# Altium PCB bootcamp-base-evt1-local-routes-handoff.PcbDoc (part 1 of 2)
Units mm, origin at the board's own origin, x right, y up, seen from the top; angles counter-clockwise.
Board outline 49.31 x 77.41 mm, 4 copper layers (Top Layer, Internal Plane 1, Internal Plane 2, Bottom Layer), stack 1.597 mm thick; 167 components, 119 nets, 1376 pads, 238 vias.
Unrouted connection lines stored in the file: 50.
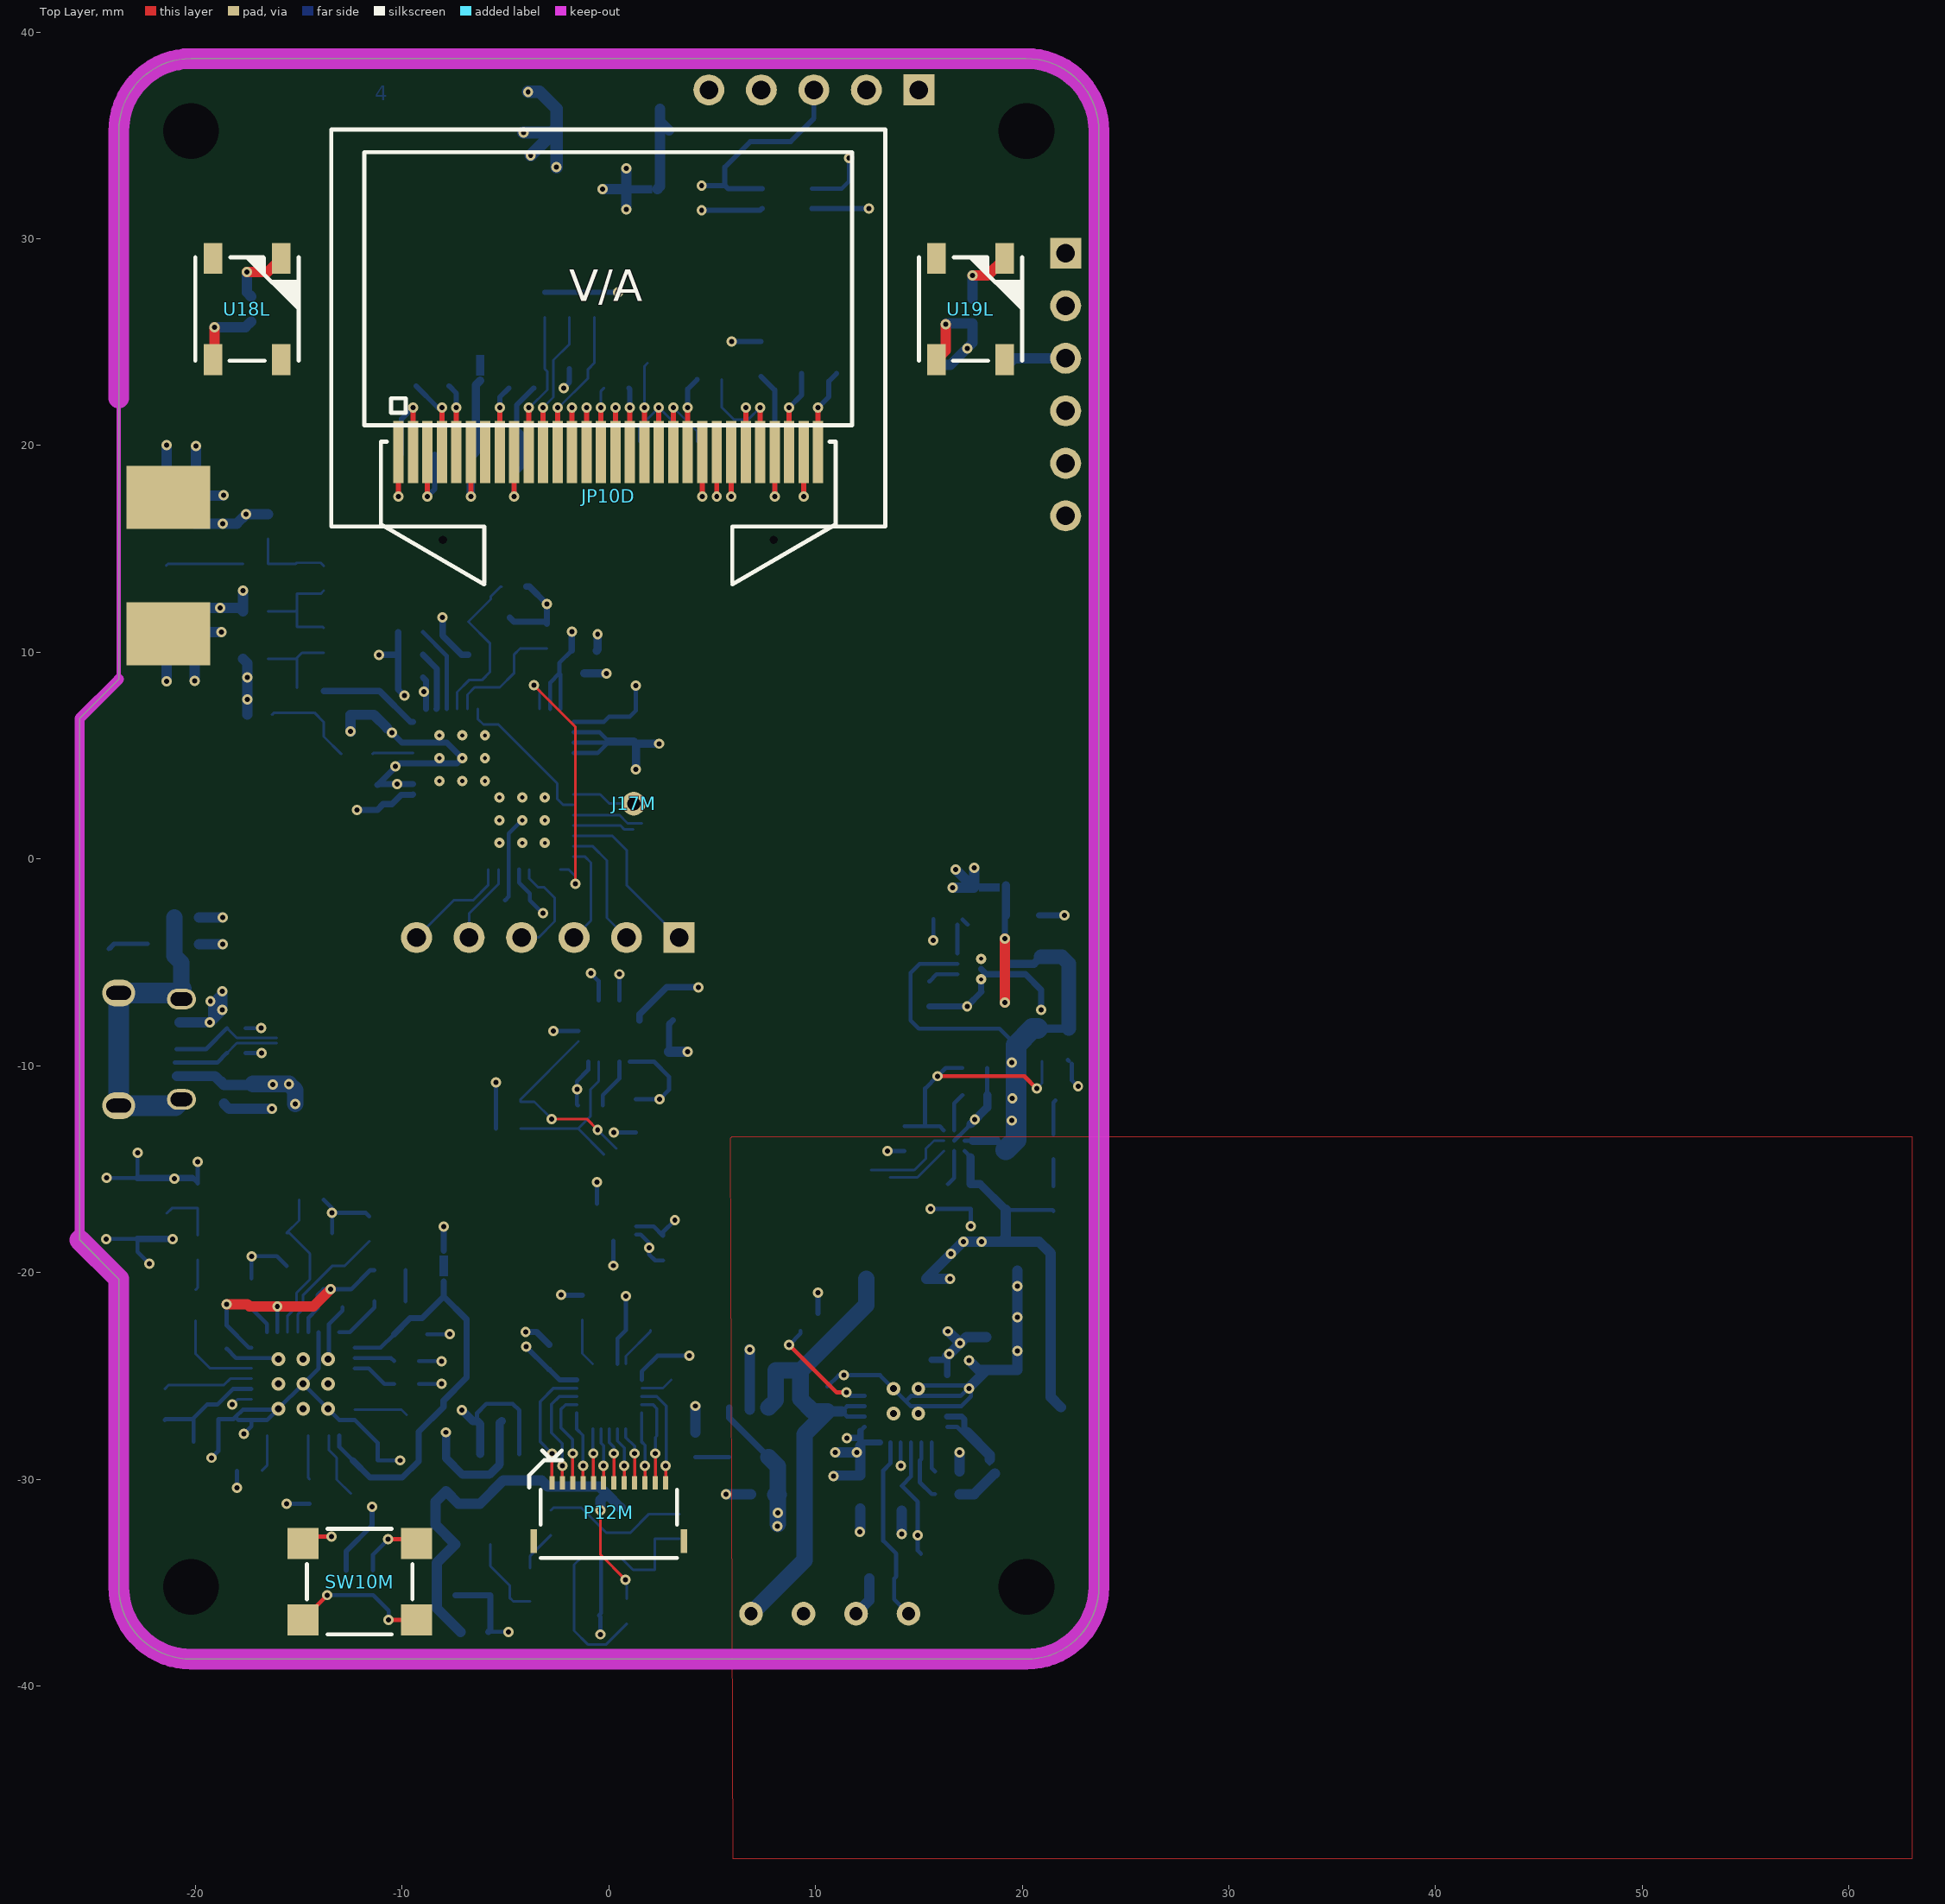
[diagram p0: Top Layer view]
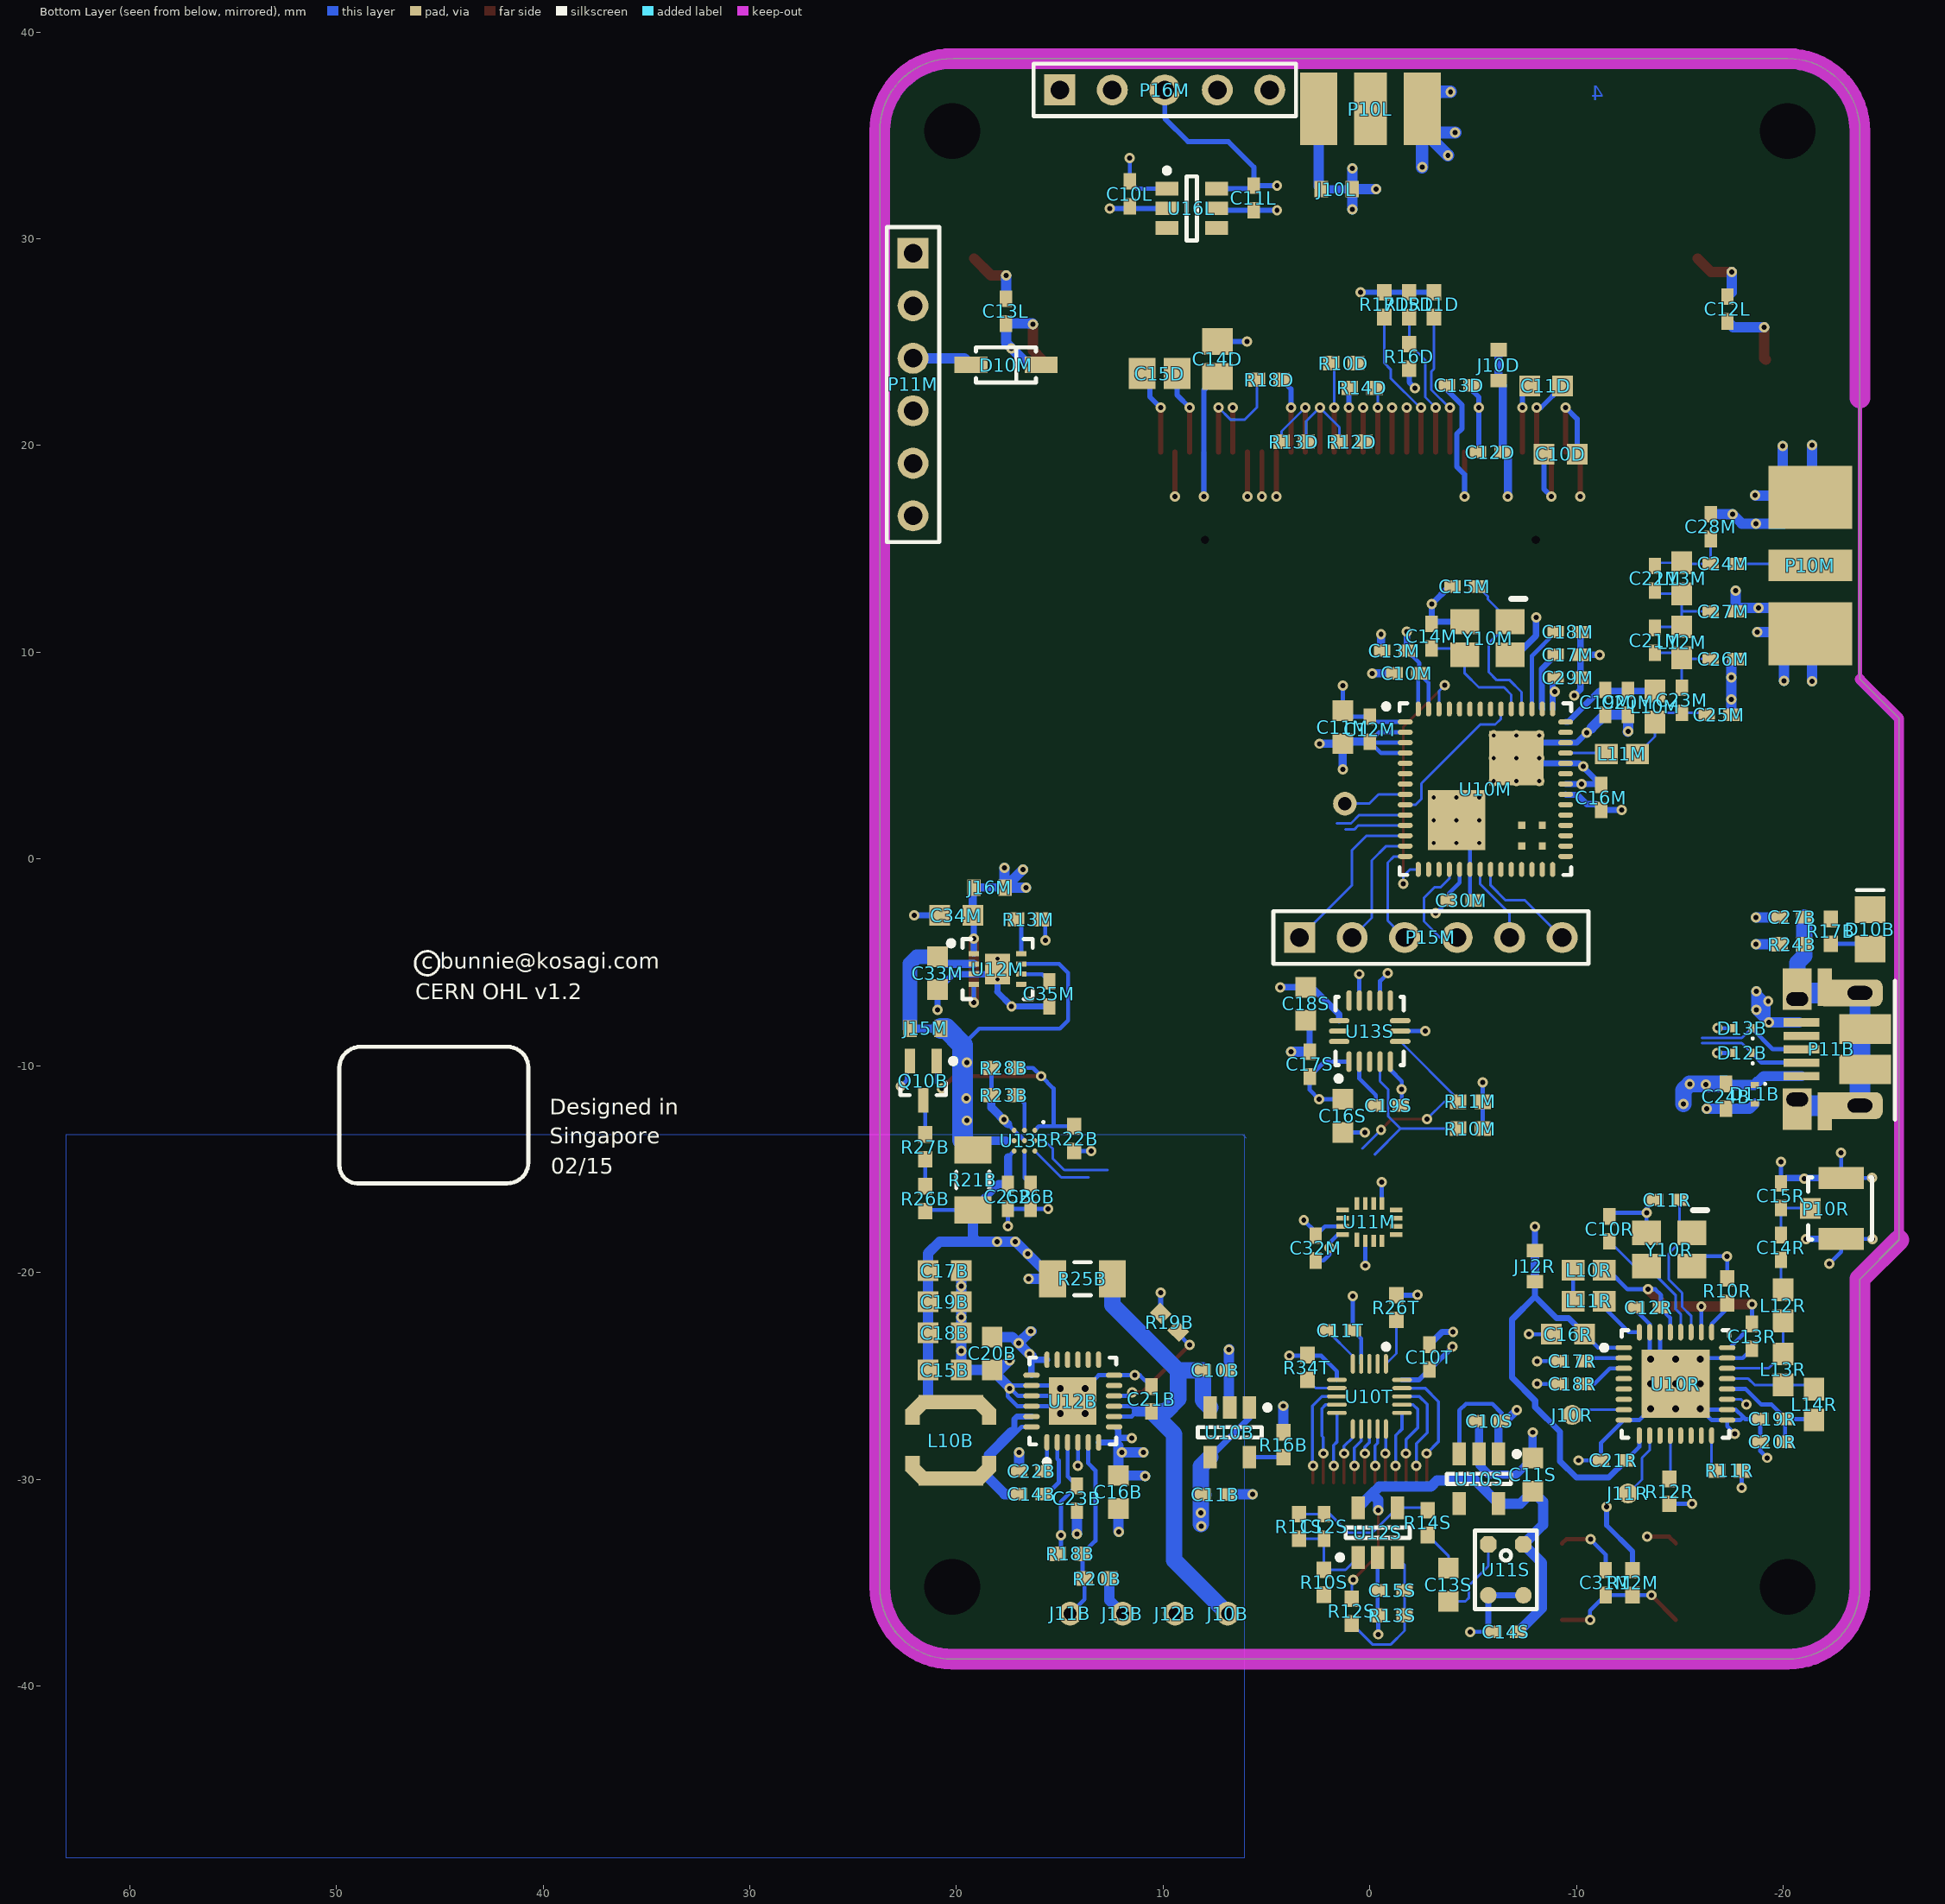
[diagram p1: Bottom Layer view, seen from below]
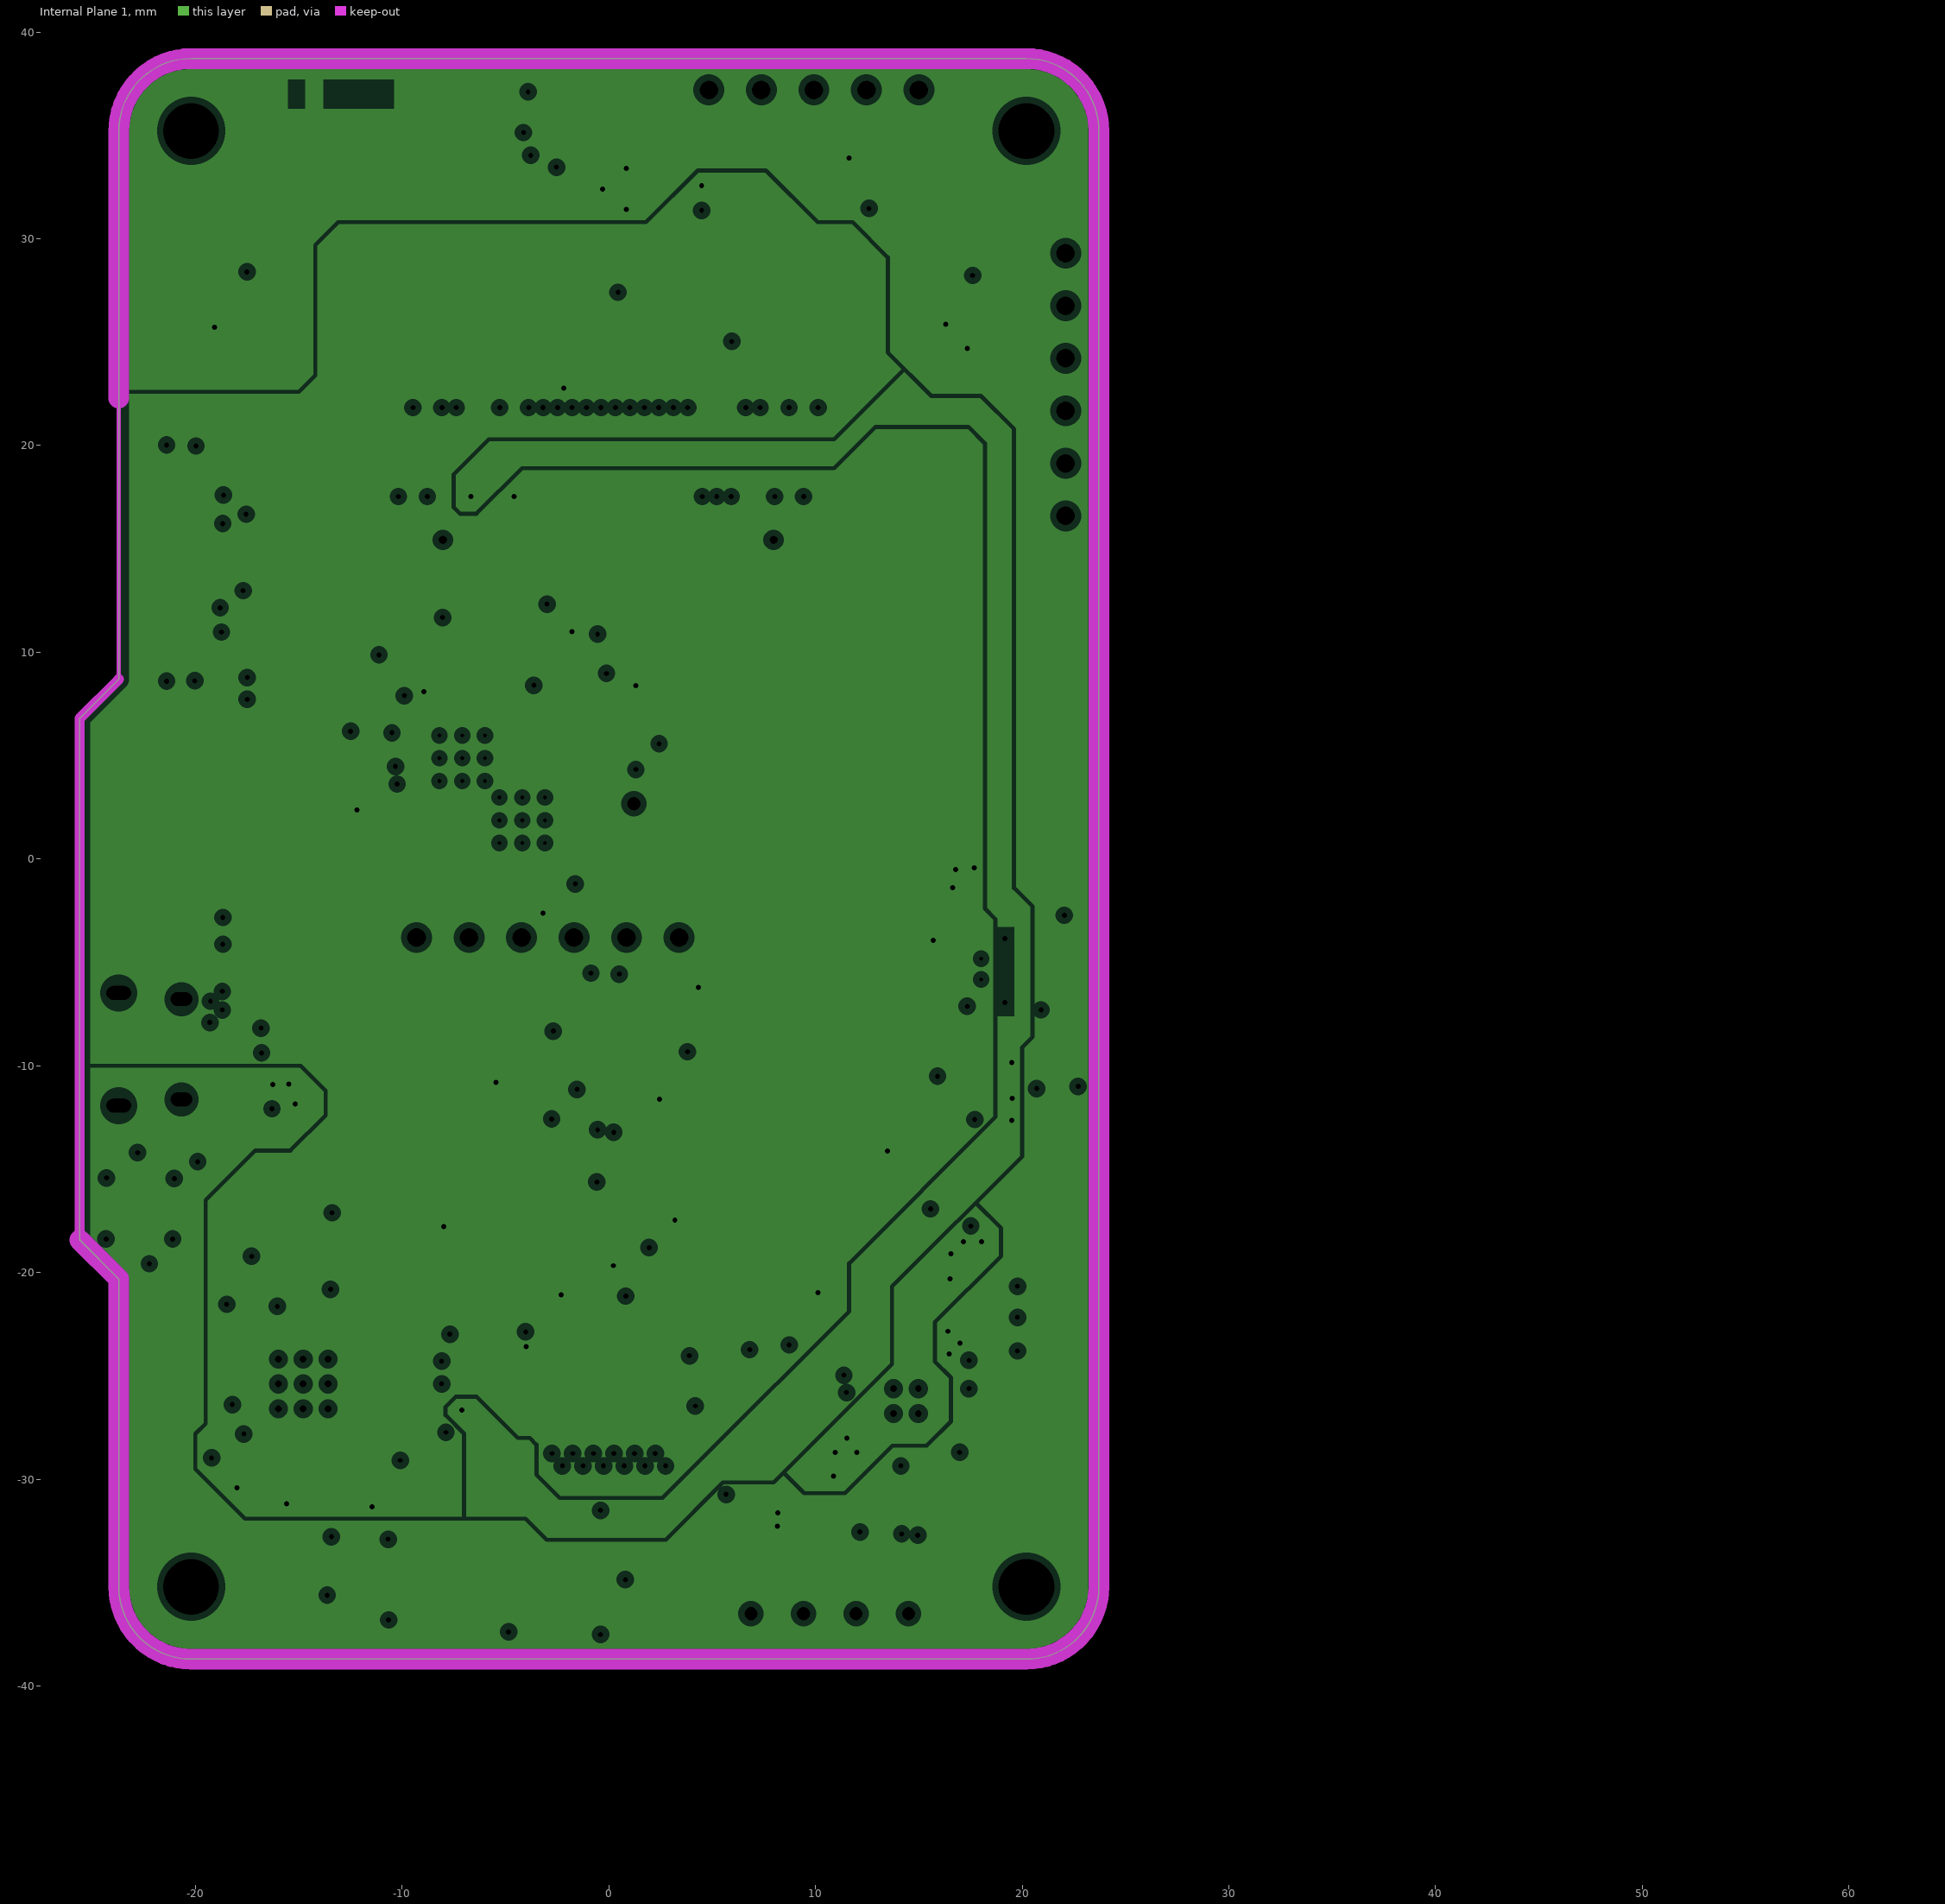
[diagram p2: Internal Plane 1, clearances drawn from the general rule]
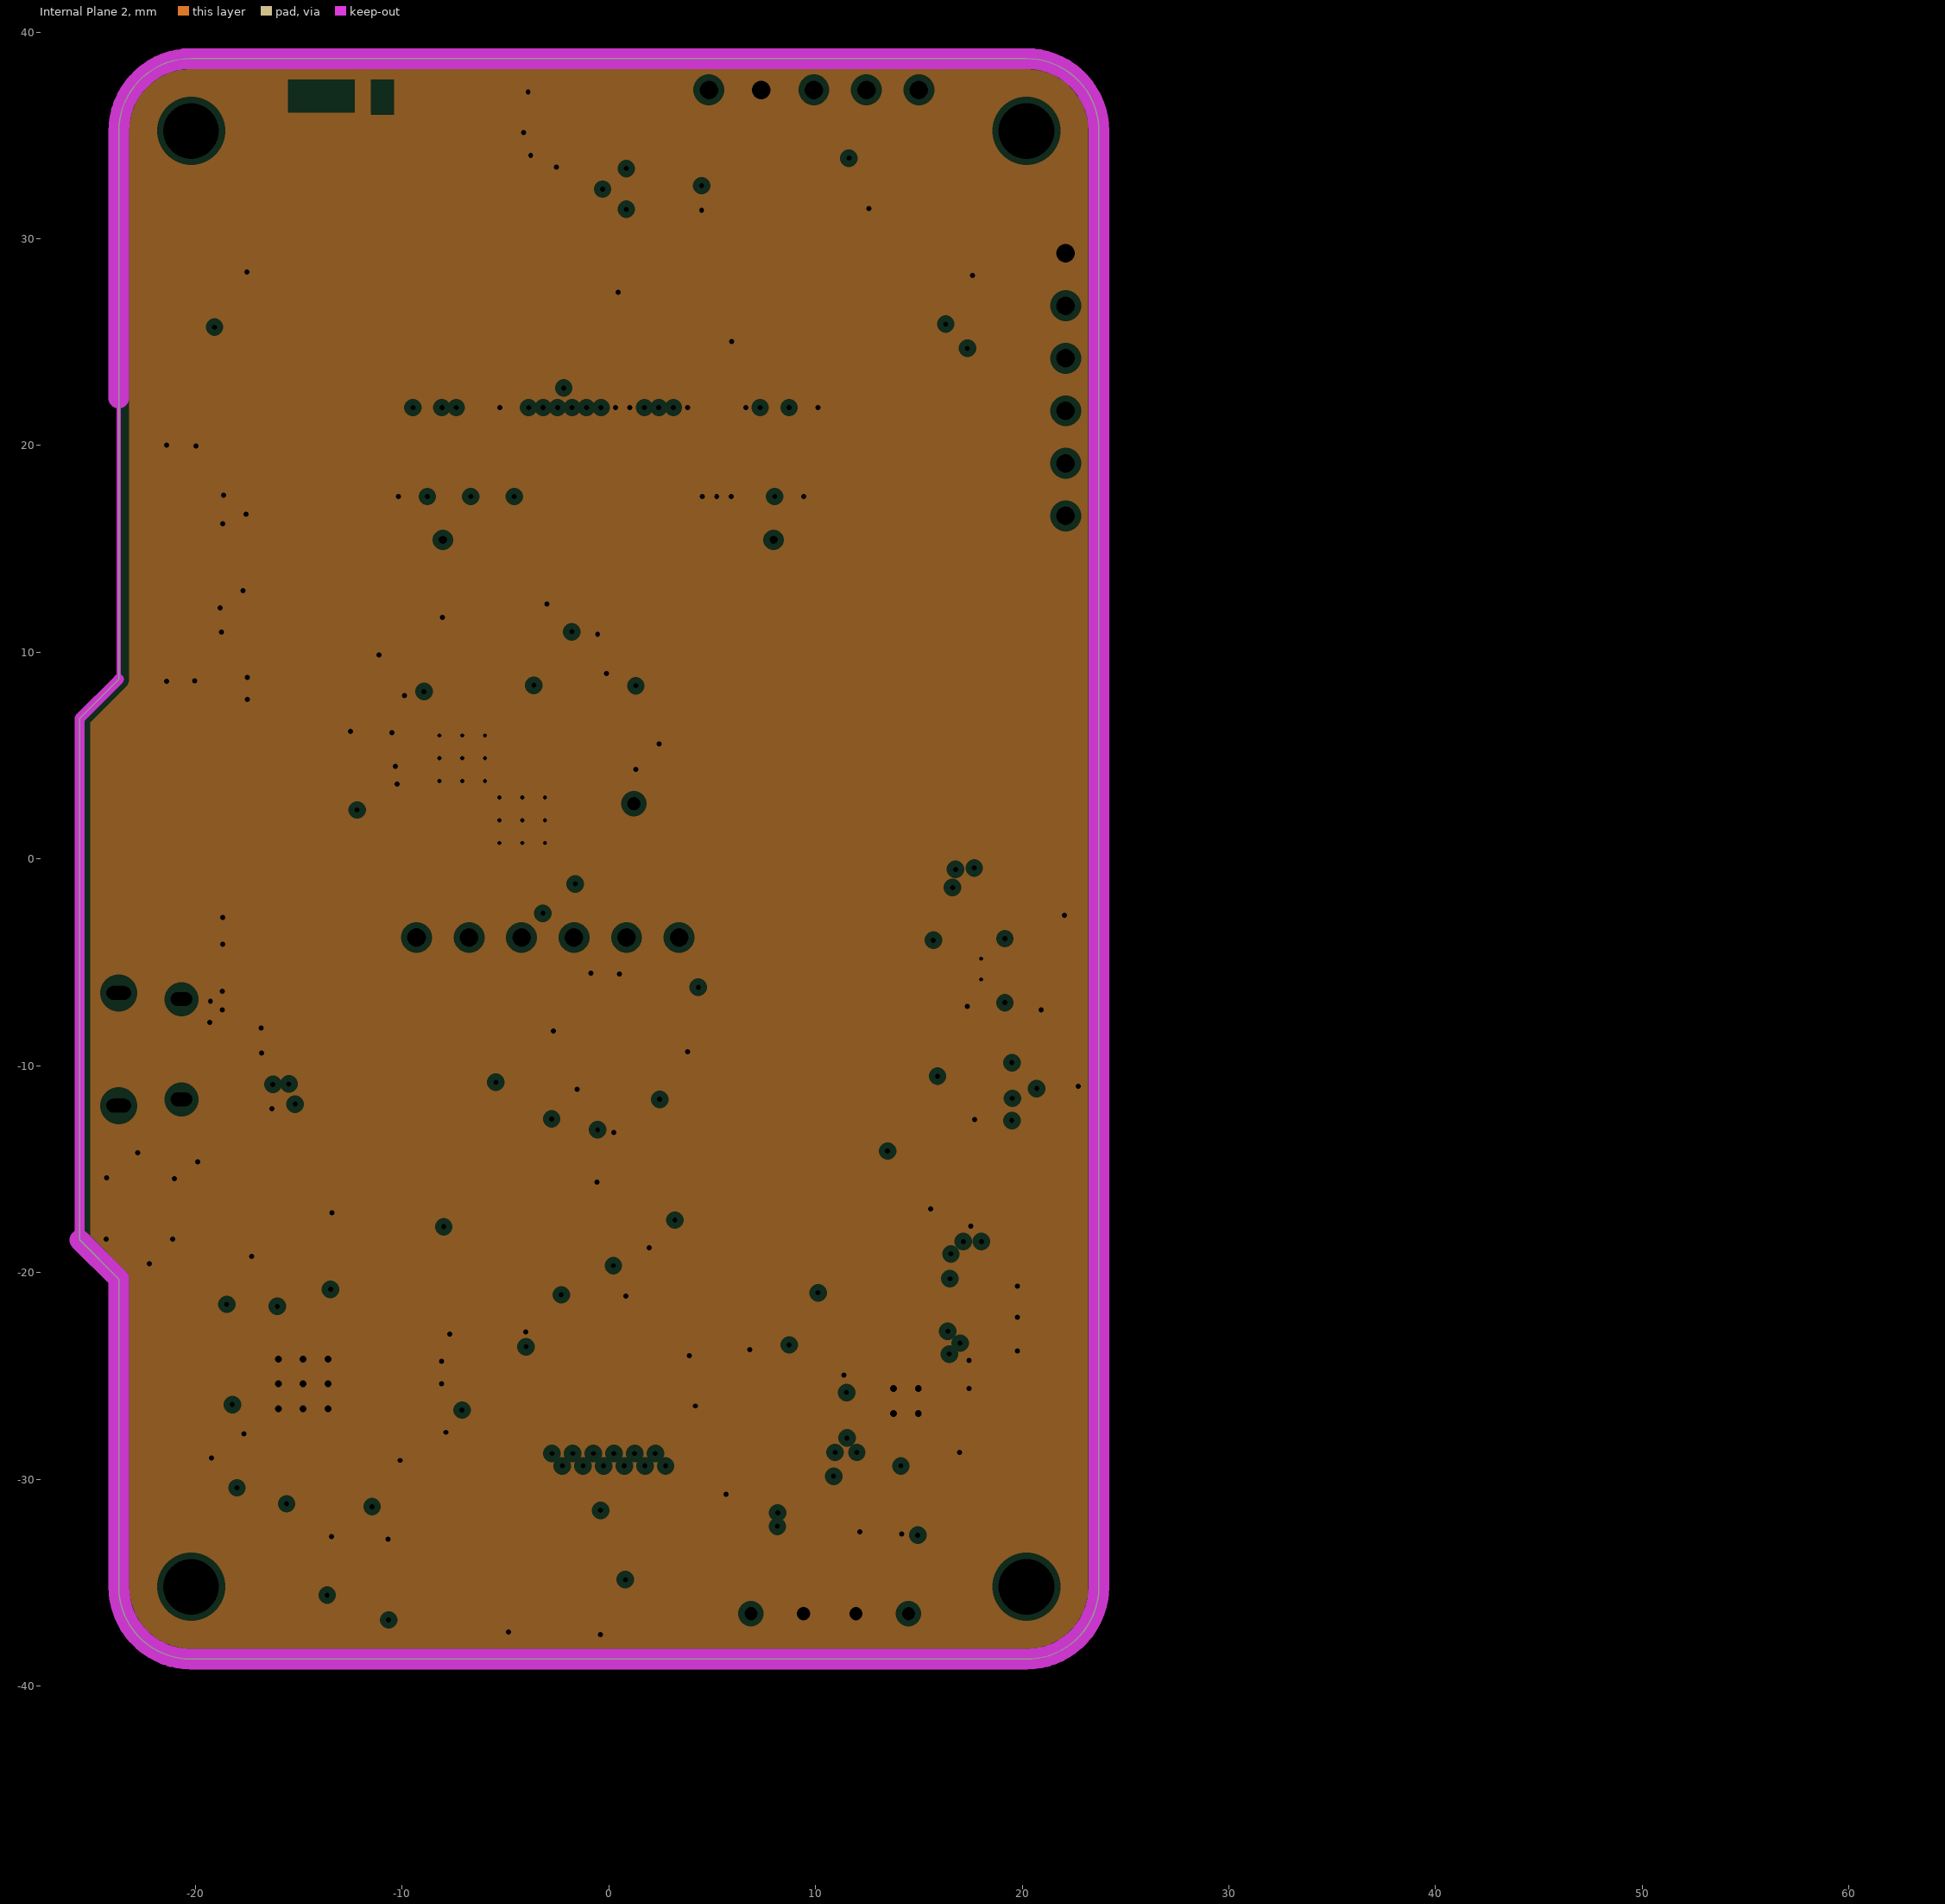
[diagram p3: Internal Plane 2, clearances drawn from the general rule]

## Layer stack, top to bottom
Top Solder: solder mask 0.0102, Solder Resist, Dk 3.5
Top Layer: signal copper 0.0356
Dielectric 1: core 0.1, FR-4, Dk 4.2
Internal Plane 1: plane copper 0.036, net P3.0V
Dielectric 3: prepreg 1.1, Dk 4.2
Internal Plane 2: plane copper 0.036, net GND
Dielectric 2: core 0.254, Dk 4.2
Bottom Layer: signal copper 0.0356
Bottom Solder: solder mask 0.0102, Solder Resist, Dk 3.5

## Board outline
-25.6,-18.417 -23.707,-20.31 -23.707,-35.2 ccw(c-20.207,-35.2) -20.207,-38.7 20.194,-38.7 ccw(c20.207,-35.2) 23.707,-35.2 23.707,-35.186 23.707,35.214 ccw(c20.207,35.214) 20.179,38.714 -20.207,38.714 ccw(c-20.207,35.214) -23.707,35.2 -23.707,8.693 -25.6,6.8

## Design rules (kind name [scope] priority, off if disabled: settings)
AssemblyTestPointUsage [All] p1 off:
AssemblyTestpoint [All] p1 off: testpointundercomponent=TRUE minsize=1.016 maxsize=2.54 preferedsize=1.524 minholesize=0 maxholesize=1.016 preferedholesize=0.813 testpointgrid=0.025 usegrid=TRUE gridtolerance=0 allowsidetop=TRUE allowsidebottom=TRUE
Clearance Poly_bt [InPoly vs InNetClass('RF')] p1: gap=0.8
Clearance Poly_diffpairs [InPoly vs InDifferentialPairClass('All Differential Pairs')] p2: gap=0.63
Clearance Poly_plane [InPoly] p3: gap=0.2
Clearance Pad_NPTH [PadIsPlated = 'False'] p4: gap=0.3
Clearance [All] p5: gap=0.125
ComponentClearance [All] p1 off: gap=0.254 collisioncheckmode=3 verticalgap=0.254 showdistances=FALSE
DiffPairsRouting [All] p1: maxlimit=0.5 minlimit=0.125 mostfreqgap=0.125 toplayer_minwidth=0.1 toplayer_maxwidth=0.1 toplayer_prefwidth=0.1 bottomlayer_minwidth=0.1 bottomlayer_maxwidth=0.1 bottomlayer_prefwidth=0.1 maxuncoupledlength=12.7
MinimumSolderMaskSliver [All] p1 off: minsoldermaskwidth=0.254
NetAntennae [All] p1 off: netantennaetolerance=0
PlaneClearance [All] p1: clearance=0.3
PlaneConnect [All] p1: planeconnectstyle=Direct reliefexpansion=0.508 reliefentries=4 reliefconductorwidth=0.254 reliefairgap=0.254
PolygonConnect PolygonConnect_via [IsVia] p1: connectstyle=Direct reliefconductorwidth=0.254 reliefentries=4 polygonreliefangle="90 Angle" airgapwidth=0.254
PolygonConnect [All] p2: connectstyle=Relief reliefconductorwidth=0.25 reliefentries=4 polygonreliefangle="90 Angle" airgapwidth=0.2
RoomDefinition 07captouch [InComponentClass('07captouch')] p1 off: confinementstyle=ConfineIn formatcopy=TRUE lockcomponents=FALSE outline 58.372,-48.063 55.972,-48.063 55.972,-40.863 58.372,-40.863
RoomDefinition 06led [InComponentClass('06led')] p2 off: confinementstyle=ConfineIn formatcopy=TRUE lockcomponents=FALSE outline 64.145,28.5 71.372,28.5 71.372,22.9 64.145,22.9
RoomDefinition 05ble [InComponentClass('05ble')] p3 off: confinementstyle=ConfineIn formatcopy=TRUE lockcomponents=FALSE outline 64.245,33.2 65.672,33.2 65.672,29.4 64.245,29.4
RoomDefinition 03sensors [InComponentClass('03sensors')] p4 off: confinementstyle=ConfineIn formatcopy=TRUE lockcomponents=FALSE outline 64.145,-0.563 63.072,-0.563 63.072,6.637 64.145,6.637
RoomDefinition 02battery [InComponentClass('02battery')] p5 off: confinementstyle=ConfineIn formatcopy=TRUE lockcomponents=FALSE outline 64.145,-19.563 66.572,-19.563 66.572,-1.663 64.145,-1.663
RoomDefinition 01mcu-radio [InComponentClass('01mcu-radio')] p6 off: confinementstyle=ConfineIn formatcopy=TRUE lockcomponents=FALSE outline 64.245,-46.763 71.072,-46.763 71.072,-20.763 64.245,-20.763
RoomDefinition 04oled [InComponentClass('04oled')] p7 off: confinementstyle=ConfineIn formatcopy=TRUE lockcomponents=FALSE outline 62.172,-44.116 60.572,-44.116 60.572,-31.216 62.172,-31.216
RoutingVias [All] p1: holewidth=0.25 width=0.5 viastyle="Through Hole" minholewidth=0.25 minwidth=0.45 maxholewidth=0.38 maxwidth=0.76
SilkToBoardRegionClearance [All] p1 off:
SilkToSilkClearance [All] p1 off: silktosilkclearance=0.254
SilkToSolderMaskClearance [IsPad] p1 off: minsilkscreentomaskgap=0.254 clearancetoexposedcopper=TRUE
SolderMaskExpansion [All] p1: expansion=0.07
Width [All] p1: maxlimit=3 minlimit=0.125 preferedwidth=0.125 minimp=50.000000 maximp=50.000000 favimp=50.000000
18 further rules are at their usual default settings.

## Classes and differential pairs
component class 07captouch: C10T C11T P12M R26T R34T U10T
component class 01mcu-radio: C10M C11M C12M C13M C14M C15M C16M C17M C18M C19M C20M C21M C22M C23M C24M C25M C26M C27M C28M C29M C30M C31M C32M C33M C34M C35M D10M J15M J16M J17M L10M L11M L12M L13M NT10M P10M P11M P15M P16M R10M R11M R12M R13M SW10M U10M U11M U12M Y10M
component class 02battery: C10B C11B C14B C15B C16B C17B C18B C19B C20B C21B C22B C23B C24B C25B C26B C27B D10B D11B D12B D13B J10B J11B J12B J13B L10B NT10B P11B Q10B R16B R17B R18B R19B R20B R21B R22B R23B R24B R25B R26B R27B R28B U10B U12B U13B
component class 03sensors: C10S C11S C12S C13S C14S C15S C16S C17S C18S C19S R10S R11S R12S R13S R14S U10S U11S U12S U13S
component class 04oled: C10D C11D C12D C13D C14D C15D J10D JP10D R10D R11D R12D R13D R14D R15D R16D R17D R18D
component class 05ble: C10R C11R C12R C13R C14R C15R C16R C17R C18R C19R C20R C21R J10R J11R J12R L10R L11R L12R L13R L14R P10R R10R R11R R12R U10R Y10R
component class 06led: C10L C11L C12L C13L J10L P10L U16L U18L U19L
net class RF: BLE_ANT BLE_ANT1 BLE_ANT2 NetC14R_1 NetC21M_1 NetC21M_2 NetC22M_2 NetC24M_2 RFIO

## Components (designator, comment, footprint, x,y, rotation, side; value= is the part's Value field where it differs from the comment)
C10B "1.0uF, 10V, X5R" CAPC1005N 7.478,-24.728 r180 bottom
C10D "1.0uF, 25V, X5R" CAPC1608N -9.228,19.584 r180 bottom
C10L "0.1uF, 25V, X5R" CAPC1005N 11.616,32.172 r270 bottom
C10M "0.1uF, 6.3V, X5R" CAPC1005N -1.792,8.979 r0 bottom
C10R "7.5pF, 50V, NP0, +/-0.5pF" CAPC1005N -11.586,-17.884 r90 bottom
C10S "0.1uF, 6.3V, X5R" CAPC1005N -5.779,-27.177 r0 bottom
C10T "0.1uF, 6.3V, X5R" CAPC1005N -2.878,-24.091 r90 bottom
C11B "1.0uF, 10V, X5R" CAPC1005N 7.478,-30.728 r180 bottom
C11D "1.0uF, 25V, X5R" CAPC1608N -8.528,22.884 r180 bottom
C11L "0.1uF, 6.3V, X5R" CAPC1005N 5.616,31.972 r270 bottom
C11M "10uF, 10V, X5R" CAPC1608N 1.308,6.379 r270 bottom
C11R "7.5pF, 50V, NP0, +/-0.5pF" CAPC1005N -14.386,-16.484 r0 bottom
C11S "4.7uF, 10V, X5R" CAPC1608N -7.879,-29.777 r90 bottom
C11T "0.1uF, 6.3V, X5R" CAPC1005N 1.422,-22.791 r180 bottom
C12D "1.0uF, 10V, X5R" CAPC1005N -5.828,19.684 r0 bottom
C12L "1.0uF, 10V, X5R" CAPC1005N -17.3,26.6 r90 bottom
C12M "0.01uF, 10V, X7R" CAPC1005N 0.008,6.279 r270 bottom
C12R "1.0uF, 10V, X5R" CAPC1005N -13.486,-21.684 r0 bottom
C12S "330pF, 10V, NP0, 5%" CAPC1005N 2.221,-32.277 r90 bottom
C13D "1.0uF, 10V, X5R" CAPC1005N -4.328,22.909 r180 bottom
C13L "1.0uF, 10V, X5R" CAPC1005N 17.6,26.5 r90 bottom
C13M "0.1uF, 6.3V, X5R" CAPC1005N -1.192,10.079 r0 bottom
C13R "1nF, 50V, X7R" CAPC1005N -18.486,-23.084 r270 bottom
C13S "10uF, 10V, X5R" CAPC1608N -3.8,-35.1 r90 bottom
C14B "0.033uF, 16V, X7R" CAPC1005N 16.372,-30.716 r0 bottom
C14D "4.7uF, 25V, X7R" CAPC2012N 7.372,24.184 r90 bottom
C14M "7.5pF, 50V, NP0, +/-0.5pF" CAPC1005N -2.992,10.779 r90 bottom
C14R "1.8pF, 50V, NP0, +/-0.10pF" CAPC1005N -19.886,-18.784 r90 bottom
C14S "0.1uF, 6.3V, X5R" CAPC1005N -6.579,-37.377 r0 bottom
C15B "10uF, 10V, X5R" CAPC1608N 20.572,-24.716 r180 bottom
C15D "4.7uF, 25V, X7R" CAPC2012N 10.172,23.484 r0 bottom
C15M "7.5pF, 50V, NP0, +/-0.5pF" CAPC1005N -4.592,13.179 r0 bottom
C15R "1.2pF, 50V, NP0, +/-0.10pF" CAPC1005N -19.886,-16.284 r270 bottom
C15S "1.0uF, 10V, X5R" CAPC1005N -1.079,-35.377 r0 bottom
C16B "10uF, 10V, X5R" CAPC1608N 12.172,-30.616 r270 bottom
C16M "0.1uF, 6.3V, X5R" CAPC1005N -11.192,2.979 r90 bottom
C16R "4.7uF, 10V, X5R" CAPC1608N -9.586,-22.984 r0 bottom
C16S "10uF, 10V, X5R" CAPC1608N 1.308,-12.421 r270 bottom
C17B "10uF, 10V, X5R" CAPC1608N 20.572,-19.916 r180 bottom
C17M "0.1uF, 6.3V, X5R" CAPC1005N -9.592,9.879 r180 bottom
C17R "0.1uF, 6.3V, X5R" CAPC1005N -9.786,-24.284 r0 bottom
C17S "0.1uF, 6.3V, X5R" CAPC1005N 2.908,-9.921 r90 bottom
C18B "10uF, 10V, X5R" CAPC1608N 20.572,-22.916 r180 bottom
C18M "0.1uF, 6.3V, X5R" CAPC1005N -9.592,10.979 r180 bottom
C18R "0.033uF, 16V, X7R" CAPC1005N -9.786,-25.384 r180 bottom
C18S "10uF, 10V, X5R" CAPC1608N 3.1,-7 r270 bottom
C19B "10uF, 10V, X5R" CAPC1608N 20.572,-21.416 r180 bottom
C19M "0.1uF, 6.3V, X5R" CAPC1005N -11.392,7.579 r270 bottom
C19R "2200pF, 50V, X7R" CAPC1005N -19.486,-27.084 r180 bottom
C19S "0.1uF, 6.3V, X5R" CAPC1005N -0.892,-11.921 r180 bottom
C20B "10uF, 10V, X5R" CAPC1608N 18.272,-23.916 r270 bottom
C20M "220pF, 10V, NP0, 5%" CAPC1005N -12.492,7.579 r270 bottom
C20R "DNP" CAPC1005N -19.486,-28.184 r180 bottom
C21B "1.0uF, 10V, X5R" CAPC1005N 10.572,-26.116 r90 bottom
C21M "0402 DNP" CAPC1005N -13.792,10.579 r90 bottom
C21R "0.1uF, 6.3V, X5R" CAPC1005N -11.786,-29.084 r0 bottom
C22B "1.0uF, 10V, X5R" CAPC1005N 16.372,-29.616 r0 bottom
C22M "0402 DNP" CAPC1005N -13.792,13.579 r90 bottom
C23B "1.0uF, 10V, X5R" CAPC1005N 14.172,-30.916 r270 bottom
C23M "6.8pF, 50V, NP0, +/-0.5pF" CAPC1005N -15.092,7.679 r90 bottom
C24B "0.1uF, 25V, X5R" CAPC1005N -17.223,-11.479 r270 bottom
C24M "100pF, 50V, NP0, 5%" CAPC1005N -17.092,14.279 r180 bottom
C25B "1.0uF, 10V, X5R" CAPC1005N 17.508,-16.321 r270 bottom
C25M "2.0pF, 50V, NP0, +/-0.25pF" CAPC1005N -16.892,6.979 r180 bottom
C26B "1.0uF, 10V, X5R" CAPC1005N 16.408,-16.321 r270 bottom
C26M "0402 DNP" CAPC1005N -17.092,9.679 r0 bottom
C27B "0.1uF, 25V, X5R" CAPC1005N -20.421,-2.823 r0 bottom
C27M "7.5pF, 50V, NP0, +/-0.5pF" CAPC1005N -17.092,11.979 r180 bottom
C28M "5.6pF, 50V, NP0, +/-0.25pF" CAPC1005N -16.492,16.079 r90 bottom
C29M "0.1uF, 6.3V, X5R" CAPC1005N -9.592,8.779 r180 bottom
C30M "0.1uF, 6.3V, X5R" CAPC1005N -4.417,-1.996 r180 bottom
C31M "0.01uF, 10V, X7R" CAPC1005N -11.408,-35 r90 bottom
C32M "0.1uF, 6.3V, X5R" CAPC1005N 2.621,-18.817 r270 bottom
C33M "4.7uF, 10V, X5R" CAPC1608N 20.908,-5.521 r270 bottom
C34M "4.7uF, 10V, X5R" CAPC1608N 20.008,-2.721 r0 bottom
C35M "0.033uF, 16V, X7R" CAPC1005N 15.508,-6.521 r90 bottom
D10B "White LED" CD2012-0805 -24.2,-3.4 r90 bottom
D10M "B140HW-7" SOD123 17.6,23.9 r180 bottom
D11B "ESD9B5.0ST5G" SOD-923 -18.623,-11.379 r270 bottom
D12B "ESD9B5.0ST5G" SOD-923 -18.023,-9.379 r0 bottom
D13B "ESD9B5.0ST5G" SOD-923 -18.023,-8.179 r0 bottom
J10B "wire hole" TP_HOLE 6.88,-36.5 r90 bottom
J10D "power tap (DNP)" RESTAP-0603 -6.228,23.884 r90 bottom
J10L "power tap (DNP)" RESTAP-0603 1.6,32.4 r0 bottom
J10R "test point (DNP)" TP_SMT_38mil -9.786,-26.884 r90 bottom
J11B "wire hole" TP_HOLE 14.5,-36.5 r180 bottom
J11R "test point (DNP)" TP_SMT_38mil -12.486,-30.684 r90 bottom
J12B "wire hole" TP_HOLE 9.42,-36.5 r0 bottom
J12R "power tap (DNP)" RESTAP-0603 -7.986,-19.684 r270 bottom
J13B "wire hole" TP_HOLE 11.96,-36.5 r270 bottom
J15M "power tap (DNP)" RESTAP-0603 21.5,-8.2 r180 bottom
J16M "power tap (DNP)" RESTAP-0603 18.4,-1.379 r180 bottom
J17M "wire hole" TP_HOLE 1.208,2.679 r180 top
JP10D "ER-OLED0.96-3W" ER-OLED0.96-FOLD -0.028,20.184 r0 top locked
L10B "2.2uH LPS4018-222" COILCRAFT_LPS4018 20.272,-28.116 r90 bottom
L10M "33nH 5% Q>8" INDC1608AN -13.792,7.379 r270 bottom
L10R "15nH, Q>35, 5%" INDC1608AN -10.586,-19.884 r180 bottom
L11M "4.7nH+/-0.3nH Q>8" INDC1608AN -12.192,5.079 r180 bottom
L11R "10uH, 300mA" INDC1608AN -10.586,-21.384 r0 bottom
L12M "6.8nH 5% Q>8" INDC1608AN -15.092,10.479 r90 bottom
L12R "3.9nH+/-0.3nH Q>8" INDC1608AN -19.986,-21.584 r90 bottom
L13M "6.8nH 5% Q>8" INDC1608AN -15.092,13.579 r90 bottom
L13R "8.2nH+/-0.3nH Q>8" INDC1608AN -19.986,-24.684 r270 bottom
L14R "5.6nH+/-0.3nH Q>8" INDC1608AN -21.486,-26.384 r270 bottom
P10L "WS2812B-PAD" LED_STRIP_PADS_SHORT -0.028,36.284 r270 bottom
P10M "SMA Edge Launch" SMA_EDGELAUNCH -21.307,14.2 r180 bottom
P10R "U.FL KAWEEI P1163-0140R" HRS_U.FL -22.8,-16.9 r270 bottom
P11B "FCI 10103594-0001LF" USB_MICRO_B_SMT -23.707,-9.2 r90 bottom
P11M "Male 2.54mm 6x1 header (DNP)" HDR1X6 22.1,29.3 r270 bottom
P12M "Header 12" KAWEEI_THD0510_12RL_GF 0,-30.5 r0 top
P15M "2.54mm header, 6 pin" HDR1X6 3.398,-3.796 r180 bottom
P16M "Header 5" HDR1X5 15,37.2 r180 bottom
Q10B "2N7002W (DNP)" SOT323-3AN 21.608,-10.721 r270 bottom
R10D "0 ohm (DNP)" RESC1005N 1.272,23.984 r180 bottom
R10M "4.7k, 1%" RESC1005N -4.863,-13.041 r180 bottom
R10R "22k, 1%" RESC1005N -17.286,-20.884 r270 bottom
R10S "2.2k, 1%" RESC1005N 2.221,-34.977 r90 bottom
R11D "10k, 1%" RESC1005N -3.103,26.809 r270 bottom
R11M "4.7k, 1%" RESC1005N -4.863,-11.741 r180 bottom
R11R "4.7k, 1%" RESC1005N -17.386,-29.584 r180 bottom
R11S "22k, 1%" RESC1005N 3.421,-32.277 r270 bottom
R12D "0 ohm (DNP)" RESC1005N 0.872,20.184 r180 bottom
R12M "1k, 1%" RESC1005N -12.708,-35 r270 bottom
R12R "4.7k, 1%" RESC1005N -14.486,-30.584 r270 bottom
R12S "47k, 1%" RESC1005N 0.877,-36.379 r90 bottom
R13D "0 ohm (DNP)" RESC1005N 3.672,20.184 r180 bottom
R13M "100k, 1%" RESC1005N 16.508,-2.921 r0 bottom
R13S "47k, 1%" RESC1005N -1.079,-36.577 r180 bottom
R14D "10k, 1% (DNP)" RESC1005N 0.372,22.784 r0 bottom
R14S "2.2k, 1%" RESC1005N -2.8,-32.1 r270 bottom
R15D "10k, 1%" RESC1005N -1.903,26.809 r270 bottom
R16B "2k, 1%" RESC1005N 4.178,-28.328 r90 bottom
R16D "10k, 1% (DNP)" RESC1005N -1.903,24.309 r90 bottom
R17B "470, 1%" RESC1005N -22.3,-3.5 r270 bottom
R17D "10k, 1%" RESC1005N -0.703,26.809 r270 bottom
R18B "9.76k, 1%" RESC1005N 14.5,-33.6 r0 bottom
R18D "390k, 1%" RESC1005N 4.872,23.184 r180 bottom
R19B "47k, 1%" RESC1005N 9.7,-22.4 r45 bottom
R20B "34.8k, 1%" RESC1005N 13.2,-34.8 r0 bottom
R21B "0 ohm 1206 (DNP)" RESC3216N 19.208,-15.521 r270 bottom
R22B "10k, 1%" RESC1005N 14.308,-13.521 r270 bottom
R23B "10k, 1%" RESC1005N 17.708,-11.421 r180 bottom
R24B "100, 1%" RESC1005N -20.421,-4.123 r0 bottom
R25B "0 ohm 1206 (DNP)" RESC3216N 13.9,-20.3 r0 bottom
R26B "10k, 1% (DNP)" RESC1005N 21.508,-16.421 r270 bottom
R26T "4.7k, 1%" RESC1005N -1.278,-21.691 r90 bottom
R27B "10k, 1% (DNP)" RESC1005N 21.508,-13.921 r270 bottom
R28B "10k, 1% (DNP)" RESC1005N 17.7,-10.1 r180 bottom
R34T "75k, 1%" RESC1005N 3.022,-24.591 r270 bottom
SW10M "5x5mm 1.6mm tall PB" SWITCH_TS-1187A -9.3,-33.1 r270 top
U10B "MCP73812T-420I/OT (DNP)" SOT-23-OT5_N 6.778,-27.728 r270 bottom
U10M "MKW01Z128CHN" KINETIS_W_QFN50P800X800X98_HS-57N -5.592,3.379 r180 bottom
U10R "NRF8001" QFN50P500X500-32VAN -14.786,-25.384 r180 bottom
U10S "LP2980IM5-3.0" SOT23-5AN -5.279,-29.977 r270 bottom
U10T "MPR121" QFN40P300X300X60-20N 0.022,-25.991 r270 bottom
U11M "FXL6408UMX" FAIRCHILD_UMLP16 0.021,-17.567 r90 bottom
U11S "SPU0409HD5H-PB" KNOWLES_SPU0409HD5H-PB -6.579,-34.377 r180 bottom
U12B "BQ24260/1/2RGE" QFN50P400X400-24VBN 14.372,-26.216 r90 bottom
U12M "LP3982ILD-3.0" LDA08C 18.008,-5.321 r180 bottom
U12S "FAN4174IS5X" SOT23-5AN -0.379,-32.577 r90 bottom
U13B "BQ27421YZFT-G1A" TI_YZF_S_XBGA_N9 16.708,-13.621 r270 bottom
U13S "MMA8452QR1" FSC_QFN_3x3x1_16_2077-02 0.008,-8.321 r90 bottom
U16L "SN74LVC1T45DBV" SOT26A-6N 8.616,31.472 r180 bottom
U18L "WS2812B" WS2812B -17.5,26.6 r90 top
U19L "WS2812B" WS2812B 17.5,26.6 r90 top
Y10M "32.000MHz" NDK_NX3225SA -6.792,11.479 r0 bottom
Y10R "16.000MHz" NDK_NX3225SA -15.586,-18.084 r0 bottom

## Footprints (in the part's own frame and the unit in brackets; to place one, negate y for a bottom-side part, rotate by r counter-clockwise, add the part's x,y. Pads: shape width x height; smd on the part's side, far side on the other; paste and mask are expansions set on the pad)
CAPC1005N [mm] "Chip Capacitor, Body 1.0x0.5mm, IPC Medium Density"
  rect 0.8x0.6 smd: 1(-0.6,0) 2(0.6,0)
  body extent -0.55,-0.3 0.55,0.3, height 0.6
CAPC1608N [mm] "Chip Capacitor, Body 1.6x0.8mm, IPC Medium Density"
  rect 1x1 smd: 1(-0.8,0) 2(0.8,0)
  body extent -0.87,-0.48 0.87,0.48, height 0.85
CAPC2012N [mm] "Chip Capacitor, Body 2.0x1.3mm, IPC Medium Density"
  rect 1.3x1.5 smd: 1(-0.85,0) 2(0.85,0)
  body extent -1.1,-0.72 1.1,0.72, height 1.1
CD2012-0805 [mm] "Chip Diode; Body 2.0 x 1.3 mm (LxW typ)"
  rect 1.3x1.5 smd: 1(-0.95,0) 2(0.95,0)
  silkscreen extent 1.9,-0.65 1.9,0.65
COILCRAFT_LPS4018 [mm] "Coilcraft SMT power inductor, shielded, high current"
  rect 0.7x3.124 smd mask+0.07: 1(-1.85,0) 2(1.85,0)
  rect 0.7x1 smd rot 135 mask+0.07: 1(-1.6,1.6) 2(1.6,-1.6)
  rect 0.7x1 smd rot 45 mask+0.07: 1(-1.6,-1.6) 2(1.6,1.6)
  rect 0.75x0.7 smd mask+0.07: 1(-1.125,-1.85) 1(-1.125,1.85) 2(1.125,-1.85) 2(1.125,1.85)
  body extent -2.05,-2.05 2.05,2.05, height 1.8
ER-OLED0.96-FOLD [mm] "ER-OLED 0.96in Direct to PCB mount, folded"
  round 0.2 hole 0.4 unplated mask+0.3: 0(-8,-4.75) 0(8,-4.75)
  rect 0.5x3 smd mask+0.07: 1(-10.15,-0.5) 2(-9.45,-0.5) 3(-8.75,-0.5) 4(-8.05,-0.5) 5(-7.35,-0.5) 6(-6.65,-0.5) 7(-5.95,-0.5) 8(-5.25,-0.5) 9(-4.55,-0.5) 10(-3.85,-0.5) 11(-3.15,-0.5) 12(-2.45,-0.5) 13(-1.75,-0.5) 14(-1.05,-0.5) 15(-0.35,-0.5) 16(0.35,-0.5) 17(1.05,-0.5) 18(1.75,-0.5) 19(2.45,-0.5) 20(3.15,-0.5) 21(3.85,-0.5) 22(4.55,-0.5) 23(5.25,-0.5) 24(5.95,-0.5) 25(6.65,-0.5) 26(7.35,-0.5) 27(8.05,-0.5) 28(8.75,-0.5) 29(9.45,-0.5) 30(10.15,-0.5)
  silkscreen extent -13.4,-6.9 13.4,15.1, body extent -13.4,-4.1 13.4,15.1, height 1.61
FAIRCHILD_UMLP16 [mm] "Fairchild 16-pin UMLP"
  rect 0.7x0.225 smd mask+0.07: 1(-0.85,0.6)
  rect 0.6x0.225 smd mask+0.07: 2(-0.9,0.2) 3(-0.9,-0.2) 4(-0.9,-0.6) 9(0.9,-0.6) 10(0.9,-0.2) 11(0.9,0.2) 12(0.9,0.6)
  rect 0.225x0.6 smd mask+0.07: 5(-0.6,-1.3) 6(-0.2,-1.3) 7(0.2,-1.3) 8(0.6,-1.3) 13(0.6,1.3) 14(0.2,1.3) 15(-0.2,1.3) 16(-0.6,1.3)
  silkscreen extent -1.25,1.55 -1.15,1.65, body extent -0.9,-1.3 0.9,1.3, height 0.55
FSC_QFN_3x3x1_16_2077-02 [mm] "16-pin non-standard Freescale QFN package"
  oval 1x0.25 smd mask+0.07: 1(-1.475,1) 2(-1.475,0.5) 3(-1.475,0) 4(-1.475,-0.5) 5(-1.475,-1) 9(1.475,-1) 10(1.475,-0.5) 11(1.475,0) 12(1.475,0.5) 13(1.475,1)
  oval 0.25x1 smd mask+0.07: 6(-0.5,-1.475) 7(0,-1.475) 8(0.5,-1.475) 14(0.5,1.475) 15(0,1.475) 16(-0.5,1.475)
  silkscreen extent -2.42,-1.65 1.65,1.65, body extent -1.5,-1.5 1.5,1.5, height 1
HDR1X5 [mm] "Connector; Header; 5 Position"
  rect 1.5x1.5 hole 0.9: 1(0,0)
  round 1.5 hole 0.9: 2(2.54,0) 3(5.08,0) 4(7.62,0) 5(10.16,0)
  silkscreen extent -1.27,-1.27 11.43,1.27
HDR1X6 [mm] "Connector; Header; 6 Position"
  rect 1.5x1.5 hole 0.9: 1(0,0)
  round 1.5 hole 0.9: 2(2.54,0) 3(5.08,0) 4(7.62,0) 5(10.16,0) 6(12.7,0)
  silkscreen extent -1.27,-1.27 13.97,1.27
HRS_U.FL [mm] "6 GHz U.FL connector (ISM band antennas)"
  rect 1.05x2.2 smd: GND(-1.475,0) GND(1.475,0)
  rect 1x1 smd: SIG(0,-1.5)
  silkscreen extent -1.5,-1.6 1.5,1.5, body extent -1.5,-1.6 1.5,1.5, height 1.24
INDC1608AN [mm] "Chip Inductor, Body 1.6x0.8mm, IPC Medium Density"
  rect 1.1x1 smd: 1(-0.75,0) 2(0.75,0)
  body extent -0.9,-0.5 0.9,0.5, height 1
KAWEEI_THD0510_12RL_GF [mm] "FPC, 12 pins, 0.5mm pitch, bottom contacts"
  rect 0.3x1.15 smd mask+0.07: 0(-3.635,-2.485) 0(3.635,-2.485)
  rect 0.25x0.65 smd mask+0.07: 1(-2.75,0.325) 2(-2.25,0.325) 3(-1.75,0.325) 4(-1.25,0.325) 5(-0.75,0.325) 6(-0.25,0.325) 7(0.25,0.325) 8(0.75,0.325) 9(1.25,0.325) 10(1.75,0.325) 11(2.25,0.325) 12(2.75,0.325)
  silkscreen extent -3.85,-3.3 3.3,1.9, body extent -3.3,-3.3 3.3,0.38, height 1
KINETIS_W_QFN50P800X800X98_HS-57N [mm] "QFN, 56-Leads, Body 8.00x8.00mm, Pitch 0.50mm, Thermal Pad 6.60x6.40mm, IPC Medium Density"
  oval 0.72x0.25 smd mask+0.07: 1(-3.88,3.25) 2(-3.88,2.75) 3(-3.88,2.25) 4(-3.88,1.75) 5(-3.88,1.25) 6(-3.88,0.75) 7(-3.88,0.25) 8(-3.88,-0.25) 9(-3.88,-0.75) 10(-3.88,-1.25) 11(-3.88,-1.75) 12(-3.88,-2.25) 13(-3.88,-2.75) 14(-3.88,-3.25) 29(3.88,-3.25) 30(3.88,-2.75) 31(3.88,-2.25) 32(3.88,-1.75) 33(3.88,-1.25) 34(3.88,-0.75) 35(3.88,-0.25) 36(3.88,0.25) 37(3.88,0.75) 38(3.88,1.25) 39(3.88,1.75) 40(3.88,2.25) 41(3.88,2.75) 42(3.88,3.25)
  oval 0.25x0.72 smd mask+0.07: 15(-3.25,-3.88) 16(-2.75,-3.88) 17(-2.25,-3.88) 18(-1.75,-3.88) 19(-1.25,-3.88) 20(-0.75,-3.88) 21(-0.25,-3.88) 22(0.25,-3.88) 23(0.75,-3.88) 24(1.25,-3.88) 25(1.75,-3.88) 26(2.25,-3.88) 27(2.75,-3.88) 28(3.25,-3.88) 43(3.25,3.88) 44(2.75,3.88) 45(2.25,3.88) 46(1.75,3.88) 47(1.25,3.88) 48(0.75,3.88) 49(0.25,3.88) 50(-0.25,3.88) 51(-0.75,3.88) 52(-1.25,3.88) 53(-1.75,3.88) 54(-2.25,3.88) 55(-2.75,3.88) 56(-3.25,3.88)
  rect 0.35x0.35 smd mask+0.07: 57(1.75,-1.75) 58(2.75,-1.75) 59(1.75,-2.75) 60(2.75,-2.75)
  rect 2.62x2.62 smd mask+0.07: 61(1.5,1.5)
  rect 2.77x2.9 smd mask+0.07: 62(-1.4,-1.5)
  silkscreen extent -4.93,-4.15 4.15,4.15, body extent -4,-4 4,4, height 0.98
KNOWLES_SPU0409HD5H-PB [mm] "Silicon MEMS microphone"
  oct 0.8x0.8 smd: 1(0.85,1.23) 4(-0.85,1.23)
  round 0.8 smd: 2(0.85,-1.23) 3(-0.85,-1.23)
  silkscreen extent -1.5,-1.9 1.5,1.9, body extent -1.5,-1.9 1.5,1.9, height 1.1
LDA08C [mm] "PSON, 8-Leads, Body 2.5x3mm, Pitch 0.5mm, NSC Recommended"
  rect 0.5x0.25 smd paste-0.125 mask+0.051: 1(-1.15,0.75) 2(-1.15,0.25) 3(-1.15,-0.25) 4(-1.15,-0.75) 5(1.15,-0.75) 6(1.15,-0.25) 7(1.15,0.25) 8(1.15,0.75)
  rect 1.2x1.5 smd paste-0.6 mask+0.051: 9(0,0)
  silkscreen extent -2.38,-1.45 1.7,1.45, body extent -1.55,-1.3 1.55,1.3, height 0.8
LED_STRIP_PADS_SHORT [mm] "Solder pads for WS2812B-style strips"
  rect 3.5x1.8 smd: 1(0,2.5) 3(0,-2.5)
  rect 3.5x1.6 smd: 2(0,0)
NDK_NX3225SA [mm] "3.2x2.5mm crystal"
  rect 1.4x1.2 smd: 1(0,0) 2(2.2,1.6) 3(2.2,0) 4(0,1.6)
  silkscreen extent -0.72,-1.1 -0.05,-1.1, body extent -0.6,-0.5 2.8,2.1, height 0.7
QFN40P300X300X60-20N [mm] "QFN, 20-Leads, Body 3.0x3.0mm (max), Pitch 0.40mm, IPC Medium Density"
  oval 0.95x0.2 smd mask+0.07: 1(-1.575,0.8) 2(-1.575,0.4) 3(-1.575,0) 4(-1.575,-0.4) 5(-1.575,-0.8) 11(1.575,-0.8) 12(1.575,-0.4) 13(1.575,0) 14(1.575,0.4) 15(1.575,0.8)
  oval 0.2x0.95 smd mask+0.07: 6(-0.8,-1.575) 7(-0.4,-1.575) 8(0,-1.575) 9(0.4,-1.575) 10(0.8,-1.575) 16(0.8,1.575) 17(0.4,1.575) 18(0,1.575) 19(-0.4,1.575) 20(-0.8,1.575)
  silkscreen extent -2.52,0.68 -2.28,0.92, body extent -1.5,-1.5 1.5,1.5, height 0.6
QFN50P400X400-24VBN [mm] "QFN, 24-Leads, Body 4x4mm, Pitch 0.5mm, IPC Medium Density"
  oval 0.8x0.25 smd: 1(-2,1.25) 2(-2,0.75) 3(-2,0.25) 4(-2,-0.25) 5(-2,-0.75) 6(-2,-1.25) 13(2,-1.25) 14(2,-0.75) 15(2,-0.25) 16(2,0.25) 17(2,0.75) 18(2,1.25)
  oval 0.25x0.8 smd: 7(-1.25,-2) 8(-0.75,-2) 9(-0.25,-2) 10(0.25,-2) 11(0.75,-2) 12(1.25,-2) 19(1.25,2) 20(0.75,2) 21(0.25,2) 22(-0.25,2) 23(-0.75,2) 24(-1.25,2)
  rect 2.3x2.3 smd: 25(0,0)
  silkscreen extent -3.07,-2.1 2.1,2.1, body extent -2.07,-2.07 2.07,2.07, height 1
QFN50P500X500-32VAN [mm] "QFN, 32-Leads, Body 5x5mm, Pitch 0.5mm, IPC Medium Density"
  oval 0.8x0.25 smd mask+0.075: 1(-2.5,1.75) 2(-2.5,1.25) 3(-2.5,0.75) 4(-2.5,0.25) 5(-2.5,-0.25) 6(-2.5,-0.75) 7(-2.5,-1.25) 8(-2.5,-1.75) 17(2.5,-1.75) 18(2.5,-1.25) 19(2.5,-0.75) 20(2.5,-0.25) 21(2.5,0.25) 22(2.5,0.75) 23(2.5,1.25) 24(2.5,1.75)
  oval 0.25x0.8 smd mask+0.075: 9(-1.75,-2.5) 10(-1.25,-2.5) 11(-0.75,-2.5) 12(-0.25,-2.5) 13(0.25,-2.5) 14(0.75,-2.5) 15(1.25,-2.5) 16(1.75,-2.5) 25(1.75,2.5) 26(1.25,2.5) 27(0.75,2.5) 28(0.25,2.5) 29(-0.25,2.5) 30(-0.75,2.5) 31(-1.25,2.5) 32(-1.75,2.5)
  rect 3.3x3.3 smd mask+0.075: 33(0,0)
  silkscreen extent -3.58,-2.6 2.6,2.6, body extent -2.58,-2.58 2.58,2.58, height 1
RESC1005N [mm] "Chip Resistor, Body 1.1x0.5mm, IPC Medium Density"
  rect 0.8x0.7 smd: 1(-0.6,0) 2(0.6,0)
  body extent -0.55,-0.3 0.55,0.3, height 0.4
RESC3216N [mm] "Chip Resistor, Body 3.2x1.6mm, IPC Medium Density"
  rect 1.3x1.8 smd: 1(-1.45,0) 2(1.45,0)
  silkscreen extent -0.4,-0.8 0.4,0.8, body extent -1.68,-0.87 1.67,0.87, height 0.71
RESTAP-0603 [mm] "0603 Power tap, cut-trace style"
  rect 0.65x0.8 smd: 1(-0.75,0) 1(0.75,0)
  Top Layer region: -0.504,0.2 0.496,0.2 0.496,-0.2 -0.504,-0.2
  body extent -0.8,-0.4 0.8,0.4, height 0.8
SMA_EDGELAUNCH [mil] "SMA Edge Launch, Generic"
  rect 160x60 smd: 1(0,0)
  rect 160x120 smd far side: 2(0,-130) 2(0,130)
  rect 160x120 smd: 2(0,-130) 2(0,130)
  body extent -75,-188 587,187, height 171
SOD123 [mm] "SOD-123; 2 Leads; Body 2.7 x 1.6 mm, (LxW)"
  rect 1.6x0.8 smd: 1(-1.7,0) 2(1.7,0)
  silkscreen extent -1.45,-0.85 1.45,0.85
SOD-923 [mm] "Molded Diode, 2-Leads, Body 0.80x0.60mm, IPC Medium Density"
  rect 0.3x0.4 smd: 1(-0.45,0) 2(0.45,0)
  silkscreen extent -0.55,0.45 -0.45,0.55, body extent -0.43,-0.33 0.42,0.33, height 0.4
SOT23-5AN [mm] "SOT23, 5-Leads, Body 2.9x1.6mm, Pitch 0.95mm, Lead Span 2.8mm, IPC Medium Density"
  rect 1.1x0.65 smd mask+0.075: 1(-1.2,0.95) 2(-1.2,0) 3(-1.2,-0.95) 4(1.2,-0.95) 5(1.2,0.95)
  silkscreen extent -1.32,-1.55 0.25,1.95, body extent -0.9,-1.55 0.9,1.55, height 1.45
SOT26A-6N [mm] "SOT23, 6-Leads, Body 2.9x1.7mm, Pitch 0.95mm, Lead Span 2.8mm, IPC Medium Density"
  rect 1.1x0.65 smd: 1(-1.2,0.95) 2(-1.2,0) 3(-1.2,-0.95) 4(1.2,-0.95) 5(1.2,0) 6(1.2,0.95)
  silkscreen extent -1.33,-1.55 0.25,1.95, body extent -0.9,-1.55 0.9,1.55, height 1.45
SOT323-3AN [mm] "SOT323, 3-Leads, Body 2.0x1.3mm, Pitch 0.65mm, Lead Span 2.1mm, IPC Medium Density"
  rect 1.2x0.5 smd: 1(-0.95,0.65) 2(-0.95,-0.65) 3(0.95,0)
  silkscreen extent -1.07,-1.1 0.7,1.57, body extent -0.7,-1.1 0.7,1.1, height 1
SOT-23-OT5_N [mm] "SOT23, 5-Leads, Body 2.9x1.6mm, Pitch 0.95mm, Lead Span 2.7mm, IPC Medium Density"
  rect 1.1x0.65 smd: 1(-1.2,0.95) 2(-1.2,0) 3(-1.2,-0.95) 4(1.2,-0.95) 5(1.2,0.95)
  silkscreen extent -1.32,-1.55 0.25,1.95, body extent -0.9,-1.55 0.9,1.55, height 1.45
SWITCH_TS-1187A [mm] "TS-1187A tact switch, Chi Fung Electronics"
  rect 1.5x1.5 smd mask+0.07: 1(0,0) 2(0,-5.5) 3(3.7,0) 4(3.7,-5.5)
  silkscreen extent -0.7,-5.3 4.4,-0.2, body extent -0.7,-5.3 4.4,-0.2, height 1.6
TI_YZF_S_XBGA_N9 [mm] "BGA, 9-Leads, Body 1.58x1.62mmx0.63mm, Pitch 0.50mm"
  round 0.25 smd mask+0.07: A1(-0.5,0.5) A2(0,0.5) A3(0.5,0.5) B1(-0.5,0) B2(0,0) B3(0.5,0) C1(-0.5,-0.5) C2(0,-0.5) C3(0.5,-0.5)
  silkscreen extent -0.94,0.86 -0.85,0.96, body extent -0.79,-0.81 0.79,0.81, height 0.63
TP_HOLE [mil] "Bare wire test point hole"
  round 45 hole 25: 1(0,0)
TP_SMT_38mil [mil] "38 mil round test point, SMT"
  round 38 smd: 1(0,0)
USB_MICRO_B_SMT [mm] "Micro B SMT footprint (based on USB-IF recommended pattern)"
  rect 1.825x0.7 smd mask+0.07: 0(-3,1.7) 0(3,1.7)
  rect 2x1.4 smd mask+0.07: 0(-2.9,3.03) 0(2.9,3.03)
  rrect50% 1.3x3.15 smd mask+0.07: 0(-2.725,0.475) 0(2.725,0.475)
  oval 1.3x1.6 hole 0.66 slot 1.2 at 90 deg mask+0.07: 0(-2.725,0) 0(2.725,0)
  oval 1x1.4 hole 0.66 slot 1.05 at 90 deg mask+0.07: 0(-2.425,3.03) 0(2.425,3.03)
  rect 1.425x2.5 smd mask+0.07: 0(-0.975,-0.25) 0(0.975,-0.25)
  rect 0.4x1.75 smd mask+0.07: 1(-1.3,2.825) 2(-0.65,2.825) 3(0,2.825) 4(0.65,2.825) 5(1.3,2.825)
  silkscreen extent -3.4,-1.7 3.3,-1.7, body extent -4.02,-2.75 4.02,3.28, height 2.85
WS2812B [mm] "3-color RGB LED with internal controller"
  rect 1.5x0.9 smd: 1(-2.45,1.65) 2(-2.45,-1.65) 3(2.45,-1.65) 4(2.45,1.65)
  silkscreen extent -2.5,-2.5 2.5,2.5, body extent -2.5,-2.5 2.5,2.5, height 1.5

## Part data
C10B C10D C10L C10M C10R C10S C10T C11B C11D C11L C11M C11R C11S C11T C12D C12L C12M C12R C12S C13D C13L C13M C13R C13S C14B C14D C14M C14R C14S C15B C15D C15M C15R C15S C16B C16M C16R C16S C17B C17M C17R C17S C18B C18M C18R C18S C19B C19M C19R C19S C20B C20M C20R C21B C21M C21R C22B C22M C23B C23M C24B C24M C25B C25M C26B C26M C27B C27M C28M C29M C30M C31M C32M C33M C34M C35M: library part "Cap Semi", "Capacitor (Semiconductor SIM Model)"
D10B: library part LED2, "White LED 0805"
D10M: library part "D Schottky", "Schottky Diode"
D11B D12B D13B: library part Tranzorb, "TVS Diode, 5V"
J10B J10D J10L J10R J11B J11R J12B J12R J13B J15M J16M J17M: library part CON1, "Connector"
JP10D: "0.96in OLED, 128x64, white"
L10B: library part "Inductor Iron", "Magnetic-Core Inductor"
L10M L10R L11M L11R L12M L12R L13M L13R L14R: library part Inductor, "chip inductor, 0603"
P10L: library part "Header 3", "Header, 3-Pin"
P10M: library part BNC, "50 ohm SMA Edge Launch Connector"
P10R: library part BNC, "U.FL connector"
P11B: library part USB_MINI-AB_1, "Micro USB B type connector"
P11M P15M: library part "Header 6", "Header, 6-Pin"
P12M: "Header, 12-Pin"
P16M: "Header, 5-Pin"
Q10B: library part MOSFET-N, "N-Channel MOSFET"
R10D R10M R10R R10S R11D R11M R11R R11S R12D R12M R12R R12S R13D R13M R13S R14D R14S R15D R16B R16D R17B R17D R18B R18D R19B R20B R21B R22B R23B R24B R25B R26B R26T R27B R28B R34T: library part Res1, "Resistor"
SW10M: library part "Header 4", "Chi Fung TS-1187A"
U10B: library part MCP73812T-420I/OT, "Simple, Miniature Single-Cell, Fully Integrated Li-Ion/Li-Polymer Charge Management Controller, 4.2V, 5-Pin SOT-23, Industrial Temperature, Tape and Reel"
U10M: "Freescale Kinetis Integrated Radio + MCU, < 1GHz"
U10R: "BLE single-chip solution"
U10S: library part LP2980M5, "50 mA SOT-23 regulator"
U10T: "Freescale 12-electrode captouch switch sensor IC"
U11M: library part FXL6408, "8-bit I2C GPIO expander"
U11S: "Knowles MEMS silicon microphone"
U12B: "3A, 30V host-controlled single cell Li-ion battery charger"
U12M: "Micropower, Ultra Low-Dropout, Low-Noise, 300mA CMOS Regulator"
U12S: "Rail-to-rail single CMOS op-amp, 5V, 3.7MHz GBW"
U13B: "System-side Impedance Track Gas Gauge"
U13S: "3-axis, 12-bit/8-bit digital accelerometer"
U16L: library part SN74LVC1T45, "Single-gate level translator"
U18L U19L: "RGB LED with integrated controller IC"
Y10M Y10R: library part XTAL, "32 MHz, 7pF CL 10ppm 3225 SMD crystal"

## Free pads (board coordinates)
  round 2.5 hole 2.7 unplated paste-5 mask+2: 0(-20.207,-35.2) 0(-20.207,35.214) 0(20.207,-35.2) 0(20.207,35.214)
  rect 2.489x0.051 on Bottom Overlay: 1(35.298,-20.93) 1(35.298,-20.879) 1(35.298,-20.828) 1(37.584,-18.542)
  rect 2.54x0.051 on Bottom Overlay: 1(35.323,-21.184) 1(35.323,-21.133) 1(35.323,-21.082) 1(35.323,-21.031) 1(35.323,-20.981) 1(35.323,-20.777) 1(35.323,-20.727) 1(35.323,-20.676) 1(35.323,-20.625) 1(35.323,-20.574) 1(35.425,-20.371) 1(39.743,-20.371) 1(39.845,-21.133) 1(39.845,-21.082) 1(39.845,-21.031) 1(39.845,-20.981) 1(39.845,-20.93) 1(39.845,-20.879) 1(39.845,-20.828) 1(39.845,-20.777) 1(39.845,-20.727) 1(39.845,-20.676) 1(39.845,-20.625) 1(39.845,-20.574)
  rect 2.591x0.051 on Bottom Overlay: 1(35.349,-21.285) 1(35.349,-21.235) 1(35.349,-20.523) 1(35.349,-20.473) 1(35.349,-20.422) 1(35.4,-21.336) 1(39.768,-21.336) 1(39.819,-21.285) 1(39.819,-21.235) 1(39.819,-21.184) 1(39.819,-20.523) 1(39.819,-20.473) 1(43.17,-13.578) 1(43.17,-13.527)
  rect 0.102x0.051 on Bottom Overlay: 1(35.425,-18.085) 1(36.492,-23.317) 1(38.676,-23.317) 1(39.743,-18.085) 1(42.078,-14.594) 1(42.18,-11.139) 1(43.043,-9.971) 1(43.45,-9.971) 1(43.755,-9.869) 1(44.009,-9.564) 1(44.415,-13.882) 1(44.872,-10.834) 1(44.872,-10.784) 1(45.126,-13.171) 1(47.057,-10.58) 1(48.022,-9.768) 1(48.276,-12.511) 1(48.936,-9.818) 1(49.139,-10.987)
  rect 0.152x0.051 on Bottom Overlay: 1(35.45,-23.622) 1(39.718,-23.622) 1(41.596,-14.492) 1(41.596,-14.441) 1(41.596,-14.39) 1(41.596,-14.34) 1(41.596,-14.289) 1(41.596,-14.238) 1(41.596,-14.187) 1(41.596,-14.136) 1(41.596,-14.086) 1(42.053,-12.511) 1(42.104,-13.781) 1(42.104,-10.885) 1(42.104,-10.834) 1(42.104,-10.784) 1(42.104,-10.733) 1(42.104,-10.682) 1(42.104,-10.631) 1(42.104,-10.58) 1(42.104,-10.53) 1(42.104,-10.479) 1(42.104,-10.428) 1(42.104,-10.377) 1(42.104,-10.326) 1(42.104,-9.971) 1(42.104,-9.92) 1(42.104,-9.869) 1(42.104,-9.818) 1(42.104,-9.768) 1(42.104,-9.717) 1(42.51,-13.882) 1(43.475,-10.022) 1(43.526,-10.072) 1(43.526,-9.666) 1(43.577,-10.123) 1(43.78,-9.818) 1(43.831,-11.393) 1(44.491,-9.971) 1(44.694,-11.088) 1(45.863,-14.136) 1(45.863,-9.768) 1(46.523,-9.564) 1(46.625,-10.072) 1(46.777,-10.276) 1(46.828,-12.562) 1(46.879,-10.377) 1(46.93,-10.428) 1(46.98,-10.479) 1(47.031,-10.53) 1(47.488,-11.444) 1(47.742,-10.885) 1(48.758,-10.022)
  rect 0.254x0.051 on Bottom Overlay: 1(35.45,-23.571) 1(35.45,-18.136) 1(36.466,-23.267) 1(38.702,-23.267) 1(39.718,-23.571) 1(39.718,-18.136) 1(41.596,-14.695) 1(41.596,-14.644) 1(41.596,-14.594) 1(42.053,-14.492) 1(42.104,-9.666) 1(42.205,-9.564) 1(42.408,-10.885) 1(42.459,-13.933) 1(42.815,-10.784) 1(42.866,-10.834) 1(42.967,-12.358) 1(43.018,-12.409) 1(43.018,-10.936) 1(43.069,-12.511) 1(43.272,-13.374) 1(43.272,-13.324) 1(43.272,-13.273) 1(43.272,-13.222) 1(43.272,-13.171) 1(43.272,-13.12) 1(43.272,-13.07) 1(43.323,-13.628) 1(43.831,-10.377) 1(43.831,-9.717) 1(43.882,-10.428) 1(43.882,-9.666) 1(43.932,-10.479) 1(43.983,-10.53) 1(44.085,-10.58) 1(44.136,-10.631) 1(44.339,-13.832) 1(44.542,-9.869) 1(44.593,-9.818) 1(44.694,-11.038) 1(44.745,-10.326) 1(44.745,-9.717) 1(44.796,-10.276) 1(44.999,-15.203) 1(44.999,-10.123) 1(45.05,-13.07) 1(45.101,-13.12) 1(45.863,-14.035) 1(45.863,-9.92) 1(45.964,-10.123) 1(46.422,-9.717) 1(46.422,-9.666) 1(46.472,-9.615) 1(46.523,-10.834) 1(46.574,-10.885) 1(46.625,-12.765) 1(46.625,-10.936) 1(46.676,-12.714) 1(46.726,-12.663) 1(46.726,-10.987) 1(46.777,-11.038) 1(46.879,-11.088) 1(47.438,-11.495) 1(47.59,-15.152) 1(47.793,-10.784) 1(47.793,-10.733) 1(47.844,-10.682) 1(47.895,-10.631) 1(47.946,-10.58) 1(48.047,-9.971) 1(48.098,-10.479) 1(48.098,-10.072) 1(48.149,-10.123) 1(48.2,-12.612) 1(48.2,-10.225) 1(48.25,-10.276) 1(48.301,-10.326) 1(48.454,-10.479) 1(48.504,-10.53) 1(48.555,-10.58) 1(48.606,-10.631) 1(48.657,-10.682) 1(48.708,-13.628) 1(48.758,-13.679) 1(48.758,-10.733) 1(48.809,-10.784) 1(48.86,-13.832) 1(48.911,-13.882) 1(48.911,-10.834) 1(48.962,-13.933) 1(49.012,-13.984) 1(49.012,-10.885) 1(49.063,-14.035) 1(49.063,-10.936) 1(49.114,-14.086) 1(49.165,-14.136)
  rect 0.356x0.051 on Bottom Overlay: 1(35.45,-23.521) 1(35.45,-18.187) 1(36.416,-23.216) 1(38.752,-23.216) 1(39.718,-18.187) 1(41.596,-14.746) 1(42.104,-14.34) 1(42.154,-9.615) 1(42.205,-10.987) 1(42.205,-10.225) 1(42.358,-14.035) 1(42.408,-13.984) 1(42.815,-12.155) 1(42.866,-12.206) 1(42.916,-14.746) 1(43.475,-14.136) 1(43.526,-14.238) 1(43.577,-14.34) 1(43.628,-14.39) 1(43.678,-14.492) 1(43.678,-14.441) 1(43.729,-14.543) 1(43.78,-14.594) 1(43.78,-11.495) 1(43.983,-11.901) 1(44.085,-12.054) 1(44.136,-12.155) 1(44.136,-12.104) 1(44.186,-12.206) 1(44.237,-12.308) 1(44.237,-12.257) 1(44.288,-12.358) 1(44.339,-12.409) 1(44.39,-12.46) 1(44.44,-12.562) 1(44.694,-9.768) 1(44.796,-12.866) 1(44.847,-12.917) 1(44.948,-10.174) 1(45.863,-13.933) 1(46.371,-13.019) 1(46.422,-12.968) 1(46.422,-10.276) 1(47.387,-11.698) 1(47.387,-11.546) 1(47.438,-14.746) 1(47.59,-15.102) 1(48.2,-12.663) 1(48.301,-12.968) 1(48.301,-10.377) 1(48.352,-13.07) 1(48.403,-13.171) 1(48.504,-13.324)
  rect 0.457x0.051 on Bottom Overlay: 1(35.45,-18.237) 1(42.764,-12.104) 1(43.78,-11.647) 1(43.831,-11.698) 1(44.136,-14.848) 1(44.237,-14.898) 1(44.339,-14.949) 1(44.44,-12.612) 1(44.898,-15.152) 1(45.914,-13.73) 1(45.914,-13.679) 1(45.964,-13.628) 1(45.964,-13.578) 1(46.015,-13.527) 1(46.015,-13.476) 1(46.066,-13.425) 1(46.117,-13.374) 1(46.168,-13.273) 1(47.336,-11.596) 1(48.149,-12.714)
  rect 0.508x0.051 on Bottom Overlay: 1(35.476,-23.47) 1(39.692,-23.47) 1(39.692,-18.237) 1(41.57,-14.848) 1(42.688,-12.054) 1(43.755,-11.596) 1(44.466,-15) 1(44.618,-15.051) 1(44.669,-10.936) 1(44.771,-15.102) 1(46.244,-10.326) 1(46.599,-10.225) 1(48.174,-12.816) 1(48.174,-12.765) 1(48.276,-10.428)
  rect 0.61x0.051 on Bottom Overlay: 1(35.476,-23.419) 1(35.476,-18.288) 1(39.692,-18.288) 1(42.739,-10.123) 1(44.618,-10.885) 1(45.99,-9.818) 1(47.615,-14.949)
  rect 0.711x0.051 on Bottom Overlay: 1(35.476,-18.339)
  rect 0.762x0.051 on Bottom Overlay: 1(35.501,-23.368) 1(39.667,-23.368) 1(39.667,-18.339) 1(47.641,-14.898) 1(48.555,-9.92)
  rect 0.864x0.051 on Bottom Overlay: 1(35.501,-23.317) 1(35.501,-18.39) 1(37.584,-17.323) 1(39.667,-23.317) 1(39.667,-18.39)
  rect 0.965x0.051 on Bottom Overlay: 1(35.501,-18.441) 1(37.584,-17.475) 1(37.584,-17.425) 1(37.584,-17.374) 1(39.667,-18.441) 1(47.742,-14.797)
  rect 1.016x0.051 on Bottom Overlay: 1(35.527,-23.267) 1(37.559,-17.526) 1(39.641,-23.267)
  rect 1.118x0.051 on Bottom Overlay: 1(35.527,-23.216) 1(35.527,-18.491) 1(37.559,-17.831) 1(39.641,-23.216) 1(39.641,-18.491) 1(48.428,-9.869)
  rect 2.337x0.051 on Bottom Overlay: 1(35.527,-21.387) 1(36.289,-19.863) 1(39.641,-21.387)
  rect 1.219x0.051 on Bottom Overlay: 1(35.527,-18.542) 1(37.559,-18.085) 1(39.641,-18.542)
  rect 2.286x0.051 on Bottom Overlay: 1(35.552,-20.32) 1(38.854,-19.863) 1(39.565,-20.32)
  rect 2.134x0.051 on Bottom Overlay: 1(35.679,-21.438) 1(36.187,-19.914) 1(38.981,-19.914) 1(39.489,-21.438)
  rect 1.829x0.051 on Bottom Overlay: 1(35.73,-23.063) 1(35.831,-22.809) 1(35.882,-22.708) 1(35.882,-21.539) 1(35.882,-20.219) 1(35.933,-21.59) 1(35.933,-20.168) 1(36.136,-22.149) 1(36.136,-22.098) 1(39.032,-22.149) 1(39.032,-22.098) 1(39.184,-20.117) 1(39.235,-22.657) 1(39.235,-21.59) 1(39.235,-21.539) 1(39.235,-20.168) 1(39.286,-22.759) 1(39.286,-22.708) 1(39.286,-20.219) 1(39.337,-22.809) 1(39.438,-23.063)
  rect 1.93x0.051 on Bottom Overlay: 1(35.73,-23.013) 1(36.035,-21.692) 1(36.035,-20.015) 1(36.136,-21.997) 1(36.136,-21.946) 1(39.032,-21.997) 1(39.032,-21.946) 1(39.133,-21.692) 1(39.133,-20.015) 1(39.184,-21.641) 1(39.438,-23.013)
  rect 2.032x0.051 on Bottom Overlay: 1(35.73,-20.269) 1(36.085,-21.793) 1(36.136,-21.895) 1(36.136,-21.844) 1(39.032,-21.895) 1(39.032,-21.844) 1(39.032,-21.793) 1(39.438,-20.269)
  rect 1.676x0.051 on Bottom Overlay: 1(35.755,-23.165) 1(36.111,-22.301) 1(42.205,-14.949)
  rect 1.778x0.051 on Bottom Overlay: 1(35.755,-23.114) 1(35.908,-22.657) 1(35.958,-22.606) 1(35.958,-22.555) 1(36.009,-22.505) 1(36.06,-22.403) 1(39.108,-22.403) 1(39.159,-22.505) 1(39.21,-22.606) 1(39.21,-22.555) 1(39.413,-23.114) 1(42.205,-10.072) 1(43.323,-12.003)
  rect 1.88x0.051 on Bottom Overlay: 1(35.755,-22.962) 1(35.755,-22.911) 1(35.806,-22.86) 1(35.857,-22.759) 1(35.857,-21.489) 1(35.958,-21.641) 1(35.958,-20.117) 1(36.009,-20.066) 1(36.111,-22.047) 1(39.006,-22.047) 1(39.159,-20.066) 1(39.311,-21.489) 1(39.362,-22.911) 1(39.362,-22.86) 1(39.413,-22.962)
  rect 1.727x0.051 on Bottom Overlay: 1(36.035,-22.454) 1(36.085,-22.352) 1(36.136,-22.251) 1(36.136,-22.2) 1(37.559,-18.39) 1(39.032,-22.301) 1(39.032,-22.251) 1(39.032,-22.2) 1(39.083,-22.352) 1(39.133,-22.454) 1(39.387,-23.165) 1(42.18,-14.898) 1(43.348,-11.952)
  rect 1.981x0.051 on Bottom Overlay: 1(36.06,-21.743) 1(36.111,-19.965) 1(37.584,-18.441) 1(39.057,-19.965) 1(39.108,-21.743)
  rect 4.674x0.051 on Bottom Overlay: 1(37.559,-19.406)
  rect 4.877x0.051 on Bottom Overlay: 1(37.559,-19.253)
  rect 5.08x0.051 on Bottom Overlay: 1(37.559,-19.101)
  rect 4.826x0.051 on Bottom Overlay: 1(37.584,-19.812) 1(37.584,-19.761) 1(37.584,-19.304)
  rect 4.724x0.051 on Bottom Overlay: 1(37.584,-19.711) 1(37.584,-19.66) 1(37.584,-19.355)
  rect 4.623x0.051 on Bottom Overlay: 1(37.584,-19.609) 1(37.584,-19.558) 1(37.584,-19.507) 1(37.584,-19.457)
  rect 4.928x0.051 on Bottom Overlay: 1(37.584,-19.203)
  rect 5.029x0.051 on Bottom Overlay: 1(37.584,-19.152)
  rect 5.131x0.051 on Bottom Overlay: 1(37.584,-19.05)
  rect 5.232x0.051 on Bottom Overlay: 1(37.584,-18.999)
  rect 5.334x0.051 on Bottom Overlay: 1(37.584,-18.949) 1(37.584,-18.898)
  rect 5.436x0.051 on Bottom Overlay: 1(37.584,-18.847) 1(37.584,-18.593)
  rect 5.537x0.051 on Bottom Overlay: 1(37.584,-18.796) 1(37.584,-18.745) 1(37.584,-18.644)
  rect 5.639x0.051 on Bottom Overlay: 1(37.584,-18.695)
  rect 2.184x0.051 on Bottom Overlay: 1(37.584,-18.491)
  rect 1.473x0.051 on Bottom Overlay: 1(37.584,-18.339) 1(42.205,-15.051)
  rect 1.27x0.051 on Bottom Overlay: 1(37.584,-18.288) 1(37.584,-18.237) 1(37.584,-18.187) 1(37.584,-18.136) 1(42.002,-10.022)
  rect 1.168x0.051 on Bottom Overlay: 1(37.584,-18.034) 1(37.584,-17.983) 1(37.584,-17.933) 1(37.584,-17.882)
  rect 1.067x0.051 on Bottom Overlay: 1(37.584,-17.78) 1(37.584,-17.729) 1(37.584,-17.679) 1(37.584,-17.628) 1(37.584,-17.577)
  rect 0.66x0.051 on Bottom Overlay: 1(39.667,-23.419)
  rect 0.406x0.051 on Bottom Overlay: 1(39.692,-23.521) 1(41.57,-14.797) 1(42.129,-14.289) 1(42.129,-14.238) 1(42.18,-14.187) 1(42.231,-14.136) 1(42.231,-10.936) 1(42.231,-10.276) 1(42.281,-14.086) 1(42.739,-11.901) 1(42.84,-14.848) 1(42.891,-14.797) 1(43.755,-11.546) 1(43.856,-14.644) 1(43.856,-11.749) 1(43.907,-14.695) 1(43.907,-11.8) 1(43.958,-14.746) 1(43.958,-11.85) 1(44.059,-14.797) 1(44.669,-10.987) 1(45.888,-13.882) 1(45.888,-13.832) 1(45.888,-13.781) 1(46.142,-13.324) 1(46.142,-10.53) 1(46.193,-13.222) 1(46.193,-10.58) 1(46.193,-10.377) 1(46.244,-13.171) 1(46.295,-13.12) 1(46.345,-13.07) 1(46.447,-9.92) 1(47.361,-11.647) 1(47.565,-15.051) 1(48.022,-14.746) 1(48.073,-9.818) 1(48.225,-12.866) 1(48.276,-12.917) 1(48.327,-13.019) 1(48.733,-9.971)
  rect 2.642x0.051 on Bottom Overlay: 1(39.794,-20.422)
  rect 0.305x0.051 on Bottom Overlay: 1(41.57,-9.971) 1(42.027,-13.73) 1(42.027,-13.679) 1(42.027,-13.628) 1(42.027,-13.476) 1(42.027,-13.425) 1(42.027,-13.374) 1(42.027,-13.324) 1(42.027,-13.273) 1(42.027,-13.222) 1(42.027,-13.171) 1(42.027,-13.12) 1(42.027,-13.07) 1(42.027,-13.019) 1(42.027,-12.968) 1(42.027,-12.917) 1(42.027,-12.866) 1(42.027,-12.816) 1(42.027,-12.612) 1(42.078,-14.441) 1(42.078,-14.39) 1(42.18,-11.038) 1(42.18,-10.174) 1(42.18,-10.123) 1(42.739,-11.85) 1(42.891,-12.257) 1(42.942,-14.695) 1(42.942,-14.644) 1(42.942,-14.594) 1(42.942,-14.543) 1(42.942,-14.492) 1(42.942,-14.441) 1(42.942,-14.39) 1(42.942,-14.34) 1(42.942,-14.289) 1(42.942,-14.238) 1(42.942,-14.187) 1(42.942,-14.136) 1(42.942,-14.086) 1(42.942,-14.035) 1(42.942,-13.984) 1(42.942,-13.933) 1(42.942,-13.882) 1(42.942,-13.832) 1(42.942,-13.781) 1(42.942,-13.73) 1(42.942,-13.679) 1(42.942,-13.628) 1(42.942,-12.308) 1(43.247,-13.019) 1(43.247,-12.968) 1(43.247,-12.917) 1(43.247,-12.866) 1(43.247,-12.816) 1(43.297,-13.476) 1(43.297,-13.425) 1(43.348,-13.832) 1(43.348,-13.781) 1(43.348,-13.73) 1(43.348,-13.679) 1(43.399,-13.984) 1(43.399,-13.933) 1(43.399,-13.882) 1(43.45,-14.086) 1(43.45,-14.035) 1(43.501,-14.187) 1(43.551,-14.289) 1(43.653,-9.514) 1(44.212,-10.682) 1(44.263,-10.733) 1(44.313,-13.781) 1(44.313,-13.73) 1(44.313,-13.679) 1(44.313,-13.628) 1(44.313,-13.476) 1(44.313,-13.425) 1(44.313,-13.374) 1(44.313,-13.324) 1(44.313,-13.273) 1(44.313,-13.222) 1(44.313,-13.171) 1(44.313,-13.12) 1(44.313,-13.07) 1(44.313,-13.019) 1(44.313,-12.968) 1(44.313,-12.917) 1(44.313,-12.866) 1(44.313,-12.816) 1(44.364,-10.784) 1(44.415,-12.511) 1(44.415,-10.834) 1(44.72,-12.816) 1(44.821,-10.225) 1(44.923,-12.968) 1(44.974,-13.019) 1(45.888,-13.984) 1(46.142,-10.479) 1(46.142,-10.428) 1(46.498,-12.917) 1(46.549,-12.866) 1(46.599,-12.816) 1(47.412,-14.695) 1(47.412,-14.644) 1(47.412,-14.594) 1(47.412,-14.543) 1(47.412,-14.492) 1(47.412,-14.441) 1(47.412,-14.39) 1(47.412,-14.34) 1(47.412,-14.289) 1(47.412,-14.238) 1(47.412,-14.187) 1(47.412,-14.136) 1(47.412,-14.086) 1(47.412,-14.035) 1(47.412,-13.984) 1(47.412,-13.933) 1(47.412,-13.882) 1(47.412,-13.832) 1(47.412,-13.781) 1(47.412,-13.73) 1(47.412,-13.679) 1(47.412,-13.628) 1(47.412,-13.578) 1(47.412,-13.527) 1(47.412,-13.476) 1(47.412,-13.425) 1(47.412,-13.374) 1(47.412,-13.324) 1(47.412,-13.273) 1(47.412,-13.222) 1(47.412,-13.171) 1(47.412,-13.12) 1(47.412,-13.07) 1(47.412,-13.019) 1(47.412,-12.968) 1(47.412,-12.917) 1(47.412,-12.866) 1(47.412,-12.816) 1(47.412,-12.765) 1(47.412,-12.714) 1(47.412,-12.663) 1(47.412,-12.612) 1(47.412,-12.562) 1(47.412,-12.511) 1(47.412,-12.46) 1(47.412,-12.409) 1(47.412,-12.358) 1(47.412,-12.308) 1(47.412,-12.257) 1(47.412,-12.206) 1(47.412,-12.155) 1(47.412,-12.104) 1(47.412,-12.054) 1(47.412,-12.003) 1(47.412,-11.952) 1(47.412,-11.901) 1(47.412,-11.85) 1(47.412,-11.8) 1(47.412,-11.749) 1(47.971,-9.92) 1(48.022,-10.53) 1(48.377,-13.12) 1(48.428,-13.222) 1(48.479,-13.273) 1(48.53,-13.374) 1(48.581,-13.476) 1(48.581,-13.425) 1(48.631,-13.527) 1(48.682,-13.578) 1(48.784,-13.73) 1(48.835,-13.781)
  rect 0.203x0.051 on Bottom Overlay: 1(41.621,-14.543) 1(42.027,-12.562) 1(42.078,-14.543) 1(42.18,-11.088) 1(42.332,-10.326) 1(42.383,-10.377) 1(42.434,-10.428) 1(42.485,-10.834) 1(42.485,-10.479) 1(42.535,-10.53) 1(42.586,-10.58) 1(42.637,-10.631) 1(42.688,-10.682) 1(42.739,-11.8) 1(42.739,-10.733) 1(42.891,-10.174) 1(42.942,-10.885) 1(42.993,-10.022) 1(43.043,-12.46) 1(43.094,-12.562) 1(43.094,-10.987) 1(43.145,-12.612) 1(43.551,-9.615) 1(43.602,-10.174) 1(43.602,-9.564) 1(43.653,-10.225) 1(43.704,-10.276) 1(43.704,-9.463) 1(43.755,-10.326) 1(43.805,-11.444) 1(43.805,-9.768) 1(43.958,-9.615) 1(44.517,-9.92) 1(44.72,-10.377) 1(45.888,-14.086) 1(45.888,-10.022) 1(45.888,-9.971) 1(45.939,-10.072) 1(45.99,-10.174) 1(46.041,-10.276) 1(46.041,-10.225) 1(46.295,-10.631) 1(46.345,-10.682) 1(46.396,-10.733) 1(46.447,-10.784) 1(46.447,-9.768) 1(46.498,-9.818) 1(46.549,-9.971) 1(46.599,-10.022) 1(46.65,-10.123) 1(46.701,-10.174) 1(46.803,-12.612) 1(46.803,-10.326) 1(46.955,-11.139) 1(47.615,-15.203) 1(47.768,-10.834) 1(48.073,-10.022) 1(48.174,-10.174) 1(48.225,-12.562) 1(49.19,-14.187)
  rect 1.626x0.051 on Bottom Overlay: 1(42.18,-15)
  rect 1.372x0.051 on Bottom Overlay: 1(42.205,-15.102)
  rect 0.051x0.051 on Bottom Overlay: 1(42.51,-10.784) 1(42.764,-11.749) 1(43.12,-11.038) 1(43.526,-9.717) 1(46.828,-12.511) 1(46.98,-11.19)
  rect 2.946x0.051 on Bottom Overlay: 1(43.247,-12.663)
  rect 2.997x0.051 on Bottom Overlay: 1(43.272,-12.714) 1(43.323,-12.765)
  rect 0.914x0.051 on Bottom Overlay: 1(46.142,-9.869) 1(47.717,-14.848)
  rect 0.559x0.051 on Bottom Overlay: 1(47.59,-15)

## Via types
v1: diameter 0.5, hole 0.25, Top Layer to Bottom Layer, tented both sides, 205 vias
v2: diameter 0.5, hole 0.2, Top Layer to Bottom Layer, 18 vias
v3: diameter 0.66, hole 0.33, Top Layer to Bottom Layer, tented top, 13 vias
v4: diameter 0.5, hole 0.2, Top Layer to Bottom Layer, tented top, 2 vias

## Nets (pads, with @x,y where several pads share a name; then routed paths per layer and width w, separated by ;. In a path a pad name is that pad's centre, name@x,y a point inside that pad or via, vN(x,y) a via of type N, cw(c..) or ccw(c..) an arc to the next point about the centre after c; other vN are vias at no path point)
ACCEL_INT: U11M.7 U13S.11
BAT_CD: U11M.12 U12B.4 | length 1.1
  Bottom Layer w0.2: U12B.4@14.122,-28.216 14.122,-29.347 v1(14.125,-29.35)
BAT_DRV: C23B.1 R17B.1 R18B.2 U12B.3 | length 6
  Bottom Layer w0.2: U12B.3@14.622,-28.216 14.622,-29.866 C23B.1@14.172,-30.316 14.947,-31.091 14.947,-33.447 R18B.2@15.1,-33.6
  other v1: 14.947,-32.7
BAT_INT: R19B.1 U11M.11 U12B.10 | length 5.6
  Top Layer w0.2: v1(8.725,-23.5) 11.025,-25.8 v1(11.5,-25.8)
  Bottom Layer w0.2: v1(8.725,-23.5) 9.276,-22.949 R19B.1@9.276,-22.824 ; v1(11.5,-25.8) 11.666,-25.966 U12B.10@12.372,-25.966
BAT_PMID: C22B.1 U12B.1 | length 1.5
  Bottom Layer w0.2: U12B.1@15.622,-28.216 15.622,-29.466 C22B.1@15.772,-29.616
BAT_POS: C10B.1 C21B.1 J10B.1 R25B.1 U10B.3 U12B.8 U12B.9 | length 26.2
  Bottom Layer w0.2: U12B.8@12.372,-26.966 11.522,-26.966 11.272,-26.716 11.522,-26.466 U12B.9@12.372,-26.466
  Bottom Layer w0.5: C21B.1@10.572,-26.716 11.272,-26.716
  Bottom Layer w0.8: J10B.1@6.88,-36.5 9.472,-33.908 9.472,-27.816 C21B.1@10.572,-26.716 9.872,-26.716 9.272,-26.116 9.272,-24.753 12.45,-21.575 R25B.1@12.45,-20.3 ; U10B.3@7.728,-26.528 8.078,-26.178 C10B.1@8.078,-24.728 9.272,-24.728
BAT_STAT: D10B.2 U12B.13
BAT_SW: C14B.2 L10B.1 U12B.23 U12B.24 | length 8.3
  Bottom Layer w0.2: U12B.24@16.372,-27.466 16.847,-27.466 18.422,-29.041 L10B.1@18.422,-29.241
  Bottom Layer w0.3: U12B.23@16.372,-26.966 17.072,-26.966 17.197,-27.091 17.197,-27.716
  Bottom Layer w0.5: C14B.2@16.972,-30.716 17.672,-30.716 L10B.1@18.672,-29.716 ; 17.322,-27.716 18.422,-28.816 L10B.1@18.422,-29.041
BAT_TS: J11B.1 R18B.1 R20B.2 U12B.5 | length 9
  Bottom Layer w0.2: U12B.5@13.622,-28.216 13.622,-29.228 13.275,-29.575 13.275,-32.975 R18B.1@13.9,-33.6 13.9,-34.7 R20B.2@13.8,-34.8 13.8,-35.8 J11B.1@14.5,-36.5
BLE_ANT: C14R.2 C15R.2 P10R.SIG | length 2.9
  Bottom Layer w0.125: P10R.SIG@-21.386,-17.134 -21.136,-16.884 C15R.2@-19.886,-16.884 C14R.2@-19.886,-18.184
BLE_ANT1: L13R.2 L14R.1 U10R.21 | length 4.4
  Bottom Layer w0.125: L14R.1@-21.486,-25.634 -21.286,-25.434 L13R.2@-19.986,-25.434 -18.611,-25.434 -18.311,-25.134 U10R.21@-17.286,-25.134
BLE_ANT2: L12R.1 L13R.1 U10R.22 | length 4.6
  Bottom Layer w0.125: L12R.1@-19.986,-22.334 L13R.1@-19.986,-23.934 -19.286,-24.634 U10R.22@-17.286,-24.634
BLE_AVDD: C12R.1 C13R.1 L10R.2 U10R.24 U10R.26 U10R.29 | length 14.6
  Top Layer w0.5: v1(-18.486,-21.534) -17.486,-21.534 -17.386,-21.634 v1(-16.036,-21.634) -14.286,-21.634 v1(-13.461,-20.809)
  Bottom Layer w0.2: v1(-18.486,-21.534) C13R.1@-18.486,-22.484 -18.486,-22.559 -17.411,-23.634 U10R.24@-17.286,-23.634 ; U10R.26@-16.036,-22.884 v1(-16.036,-21.634) ; U10R.29@-14.536,-22.884 -14.536,-22.184 -14.086,-21.734 C12R.1@-14.086,-21.684 -14.086,-21.084 -13.811,-20.809 v1(-13.461,-20.809) -12.461,-20.809 -11.536,-19.884 L10R.2@-11.336,-19.884
BLE_IREF: R10R.2 U10R.25 | length 1.7
  Bottom Layer w0.2: R10R.2@-17.286,-21.484 -17.286,-21.734 -16.536,-22.484 U10R.25@-16.536,-22.884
